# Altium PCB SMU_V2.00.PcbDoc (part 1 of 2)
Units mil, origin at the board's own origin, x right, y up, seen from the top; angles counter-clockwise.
Board outline 8661.42 x 7437.01 mil, 4 copper layers (Component Side, Ground Plane, Power Plane, Solder Side), stack 33.234 mil thick; 223 components, 143 nets, 756 pads, 732 vias.
Unrouted connection lines stored in the file: 6.
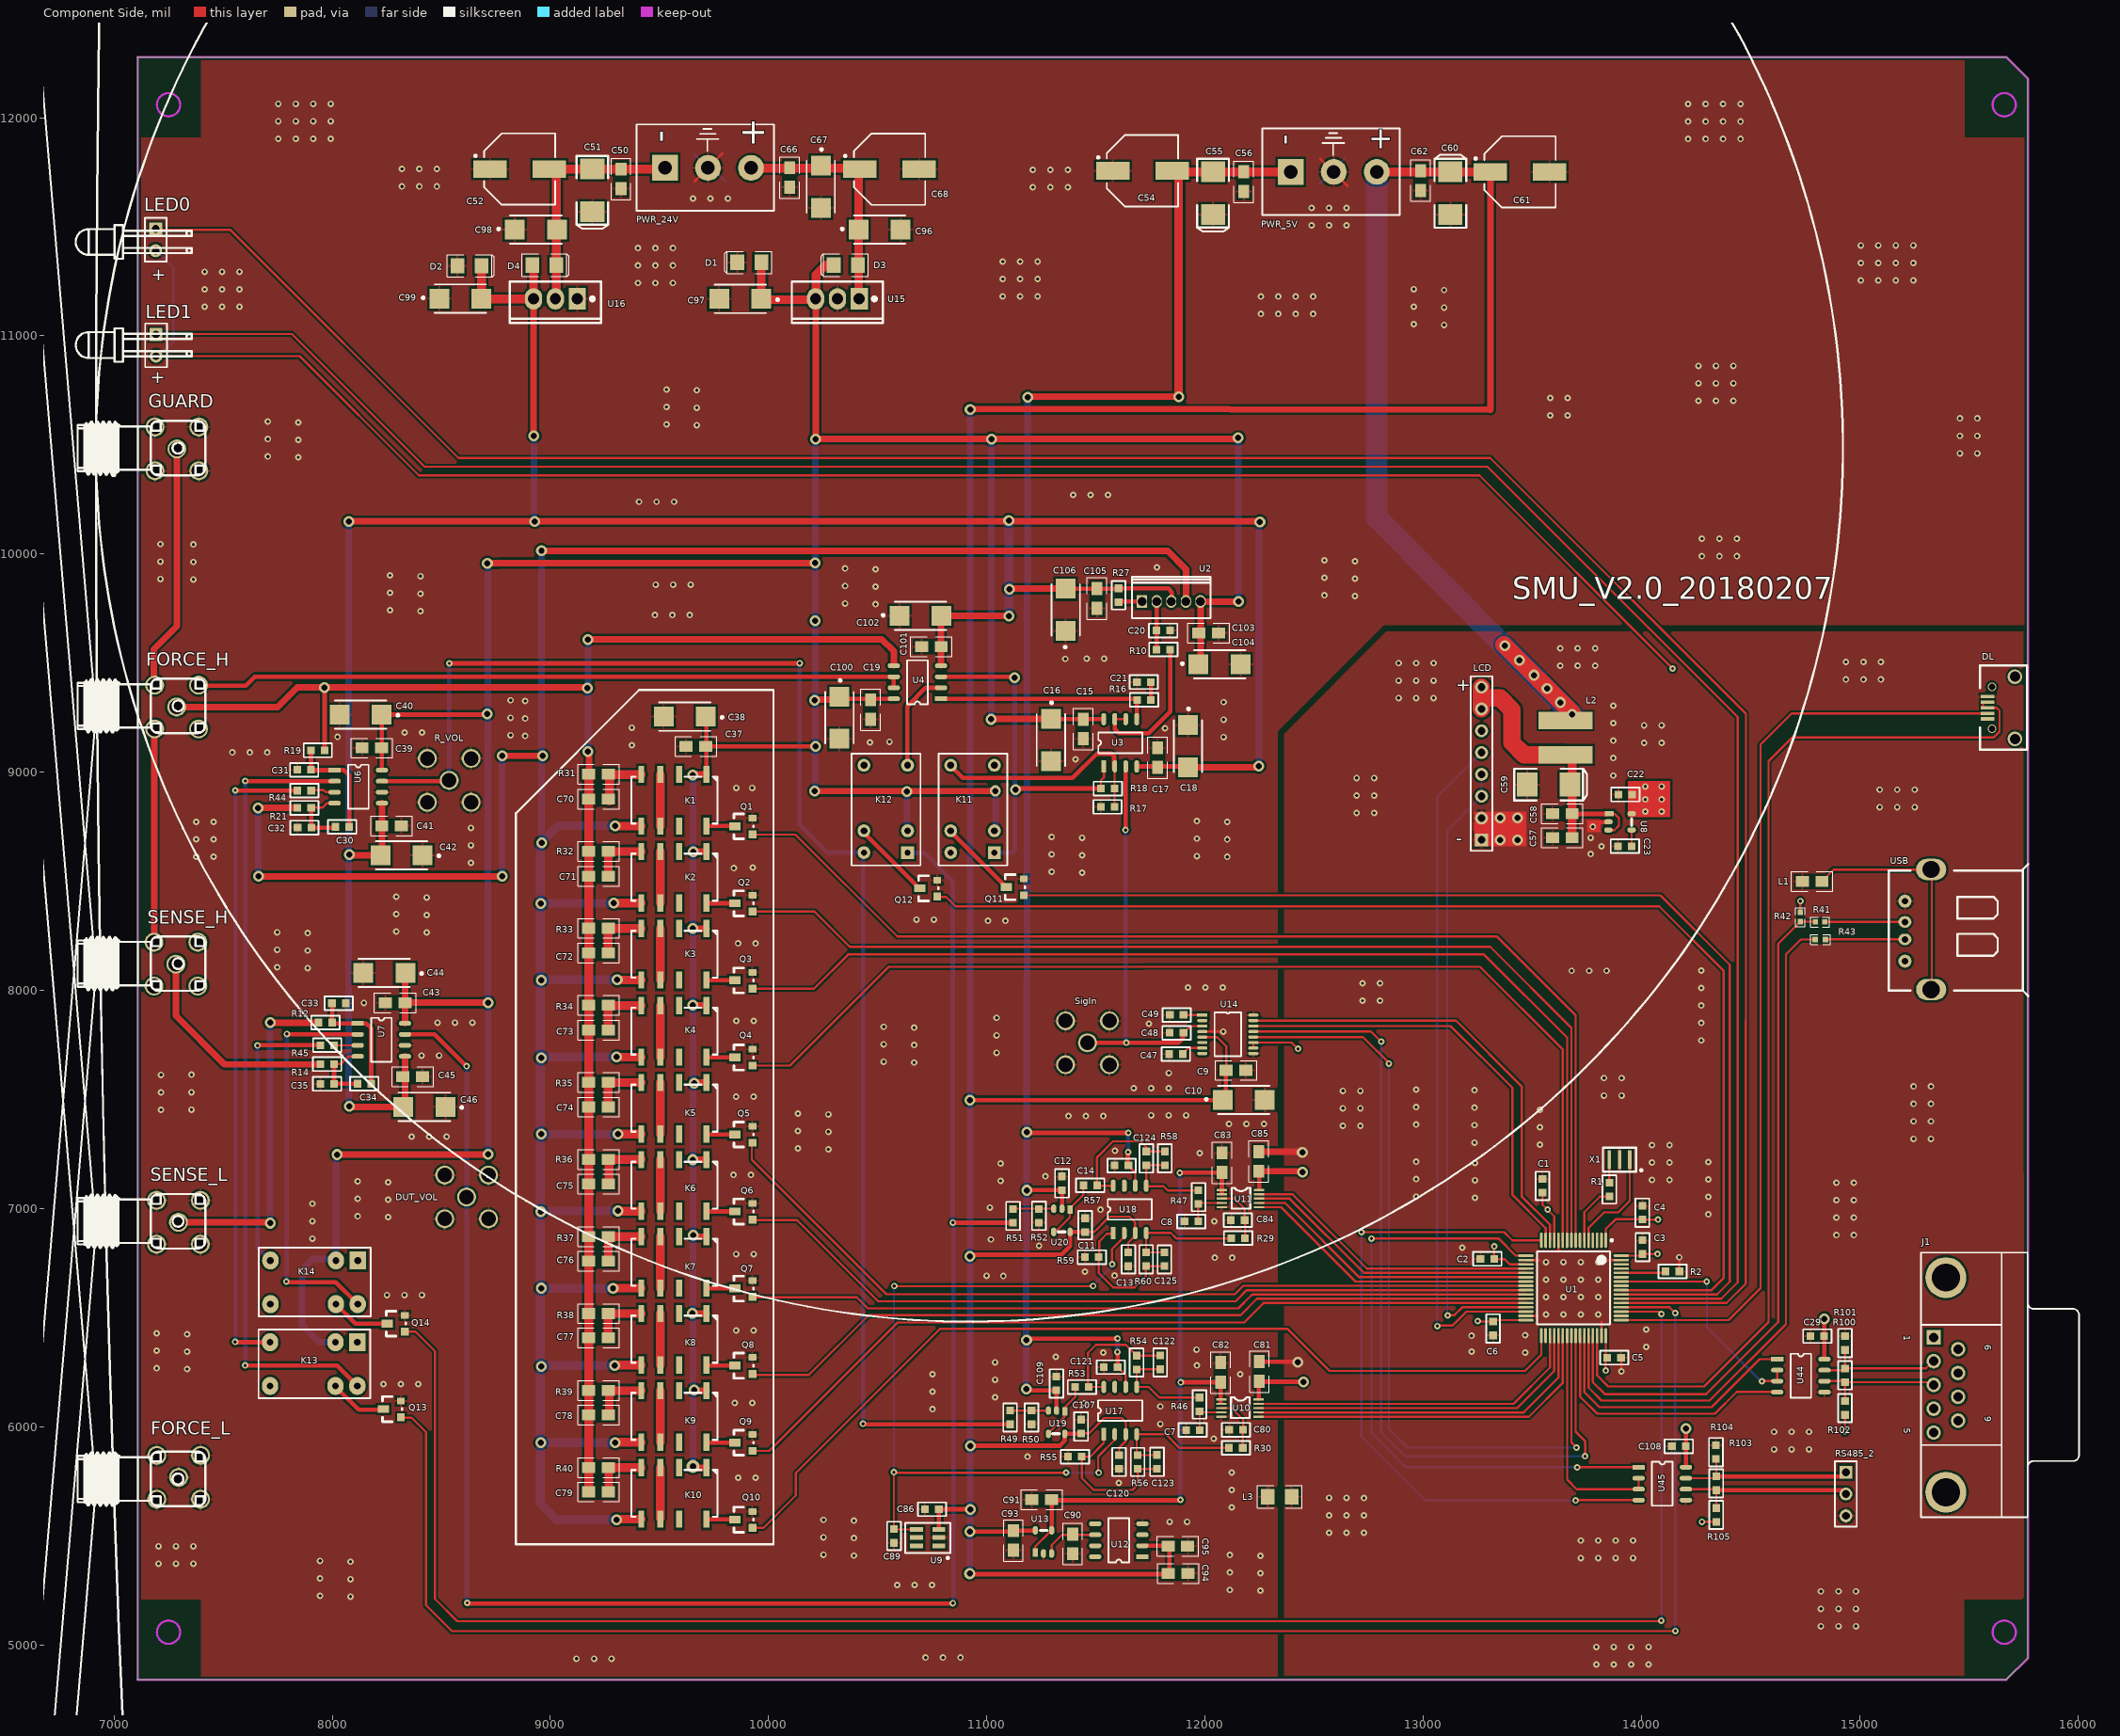
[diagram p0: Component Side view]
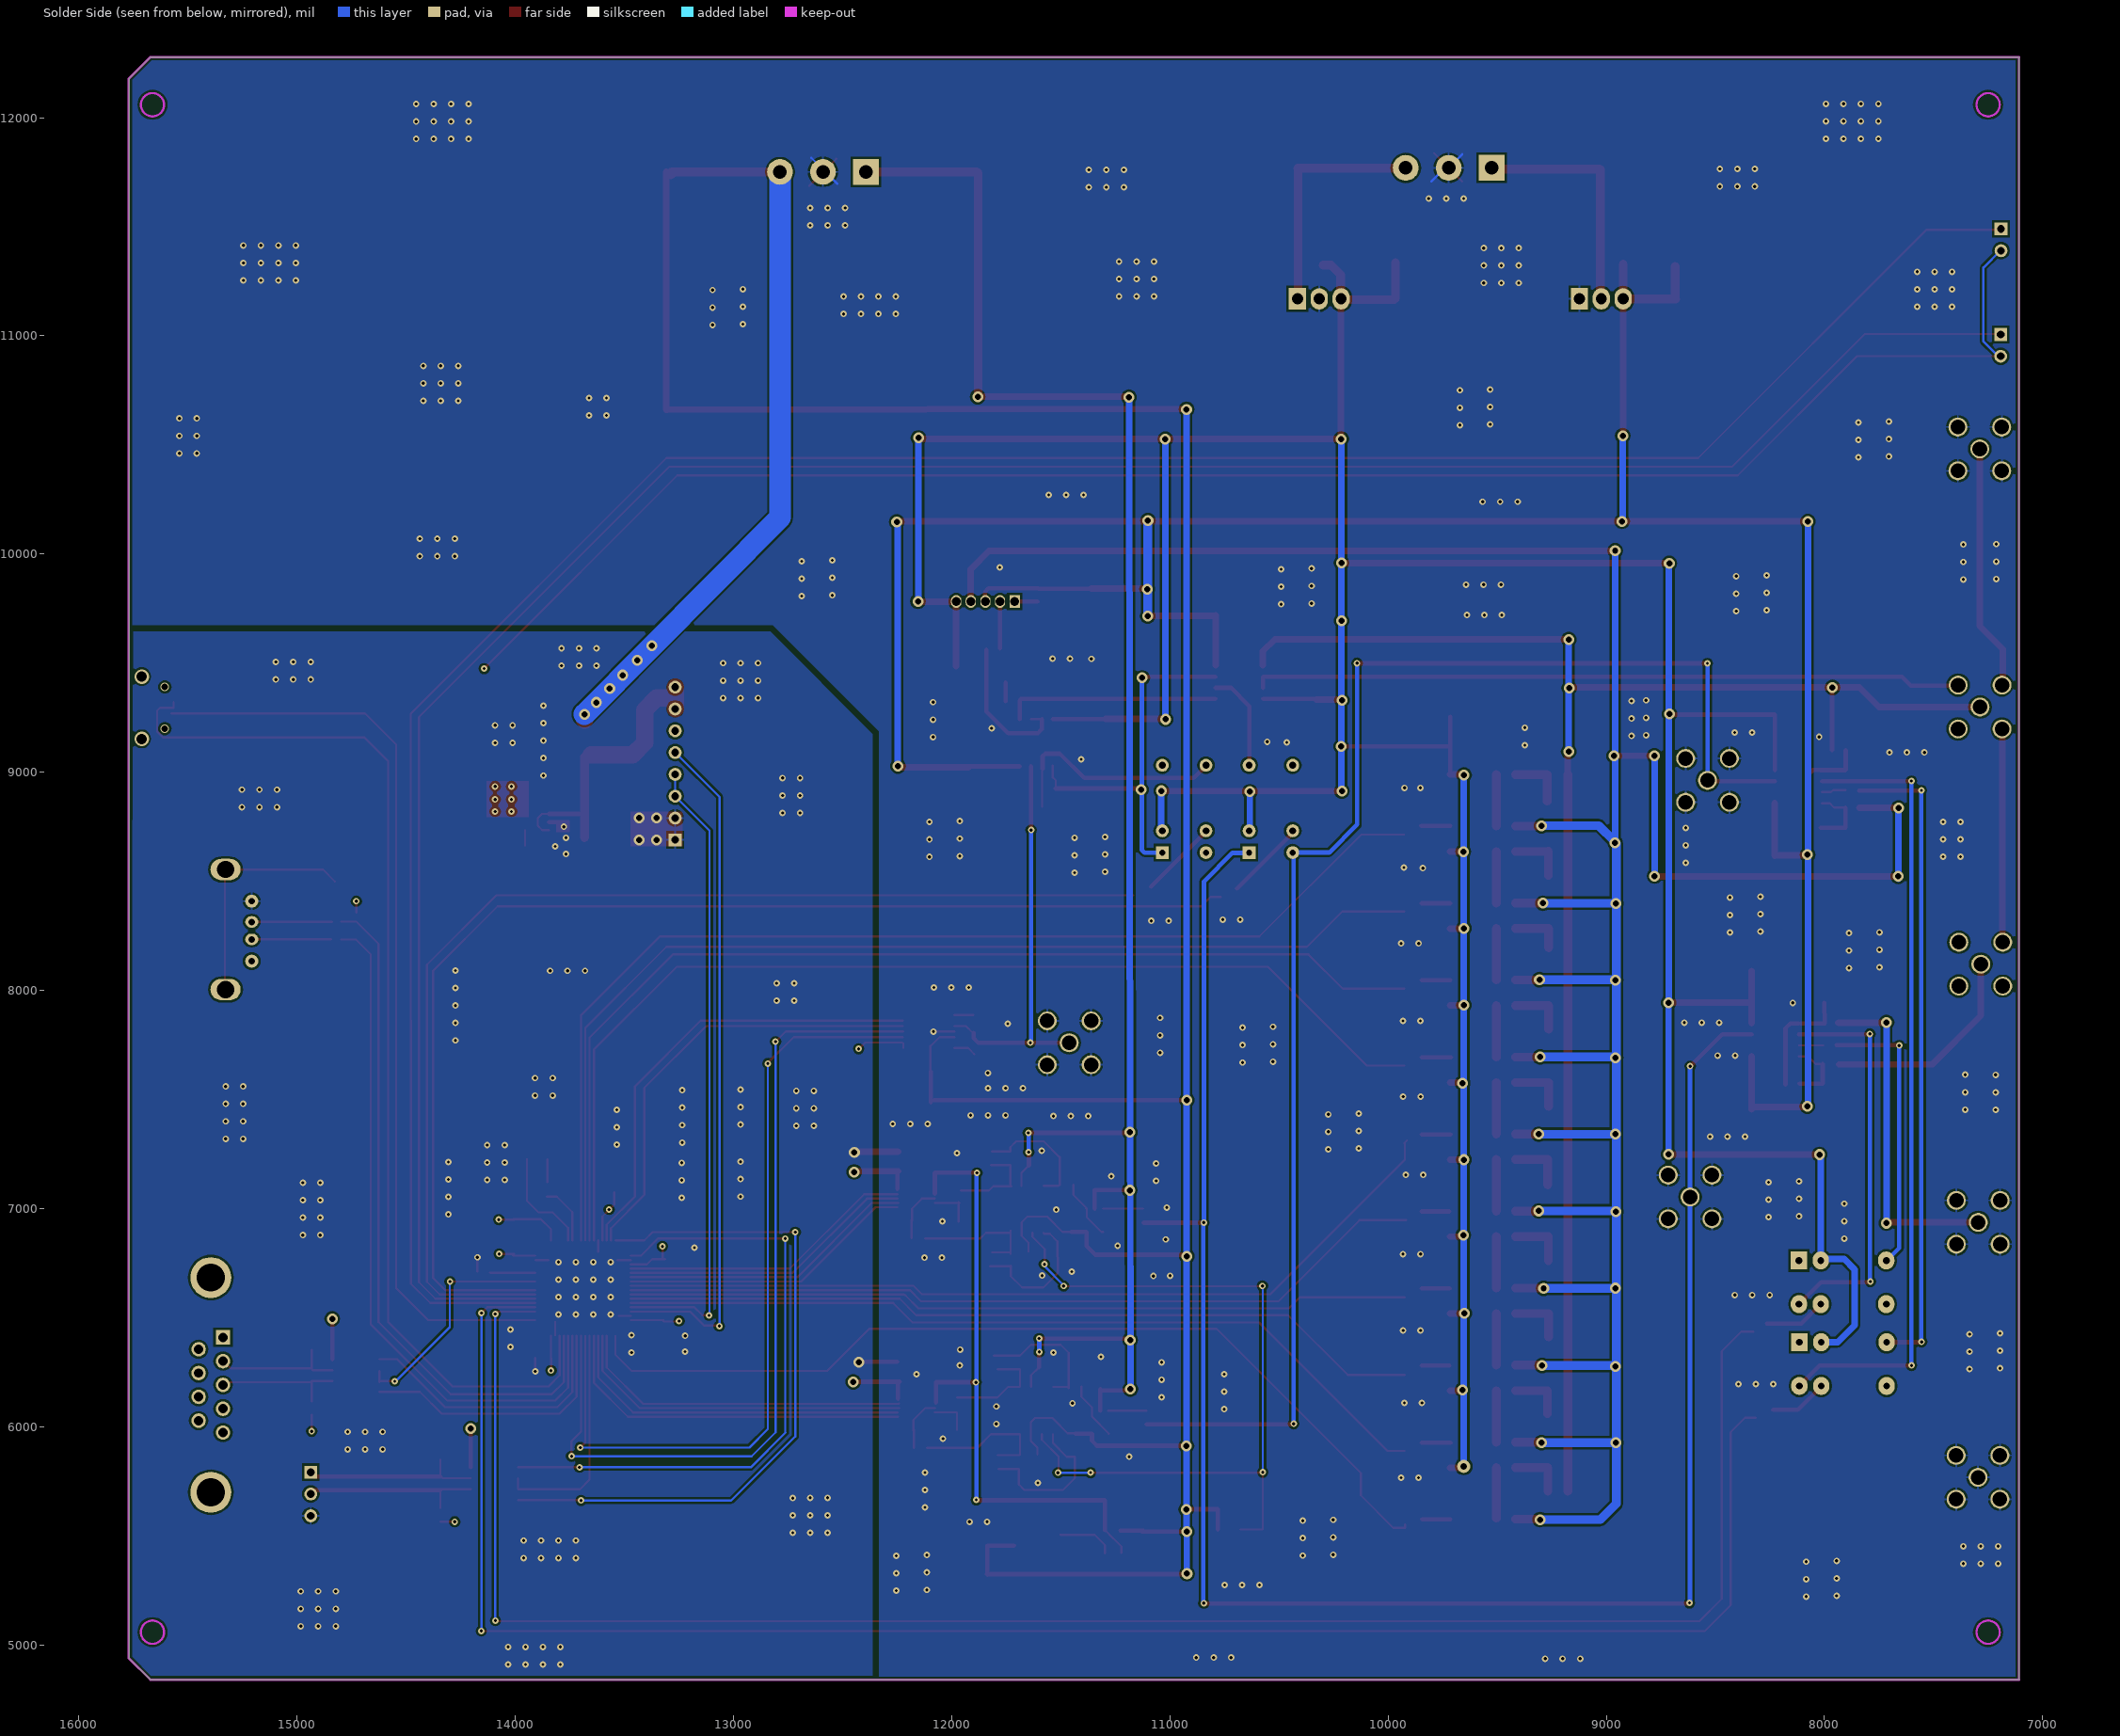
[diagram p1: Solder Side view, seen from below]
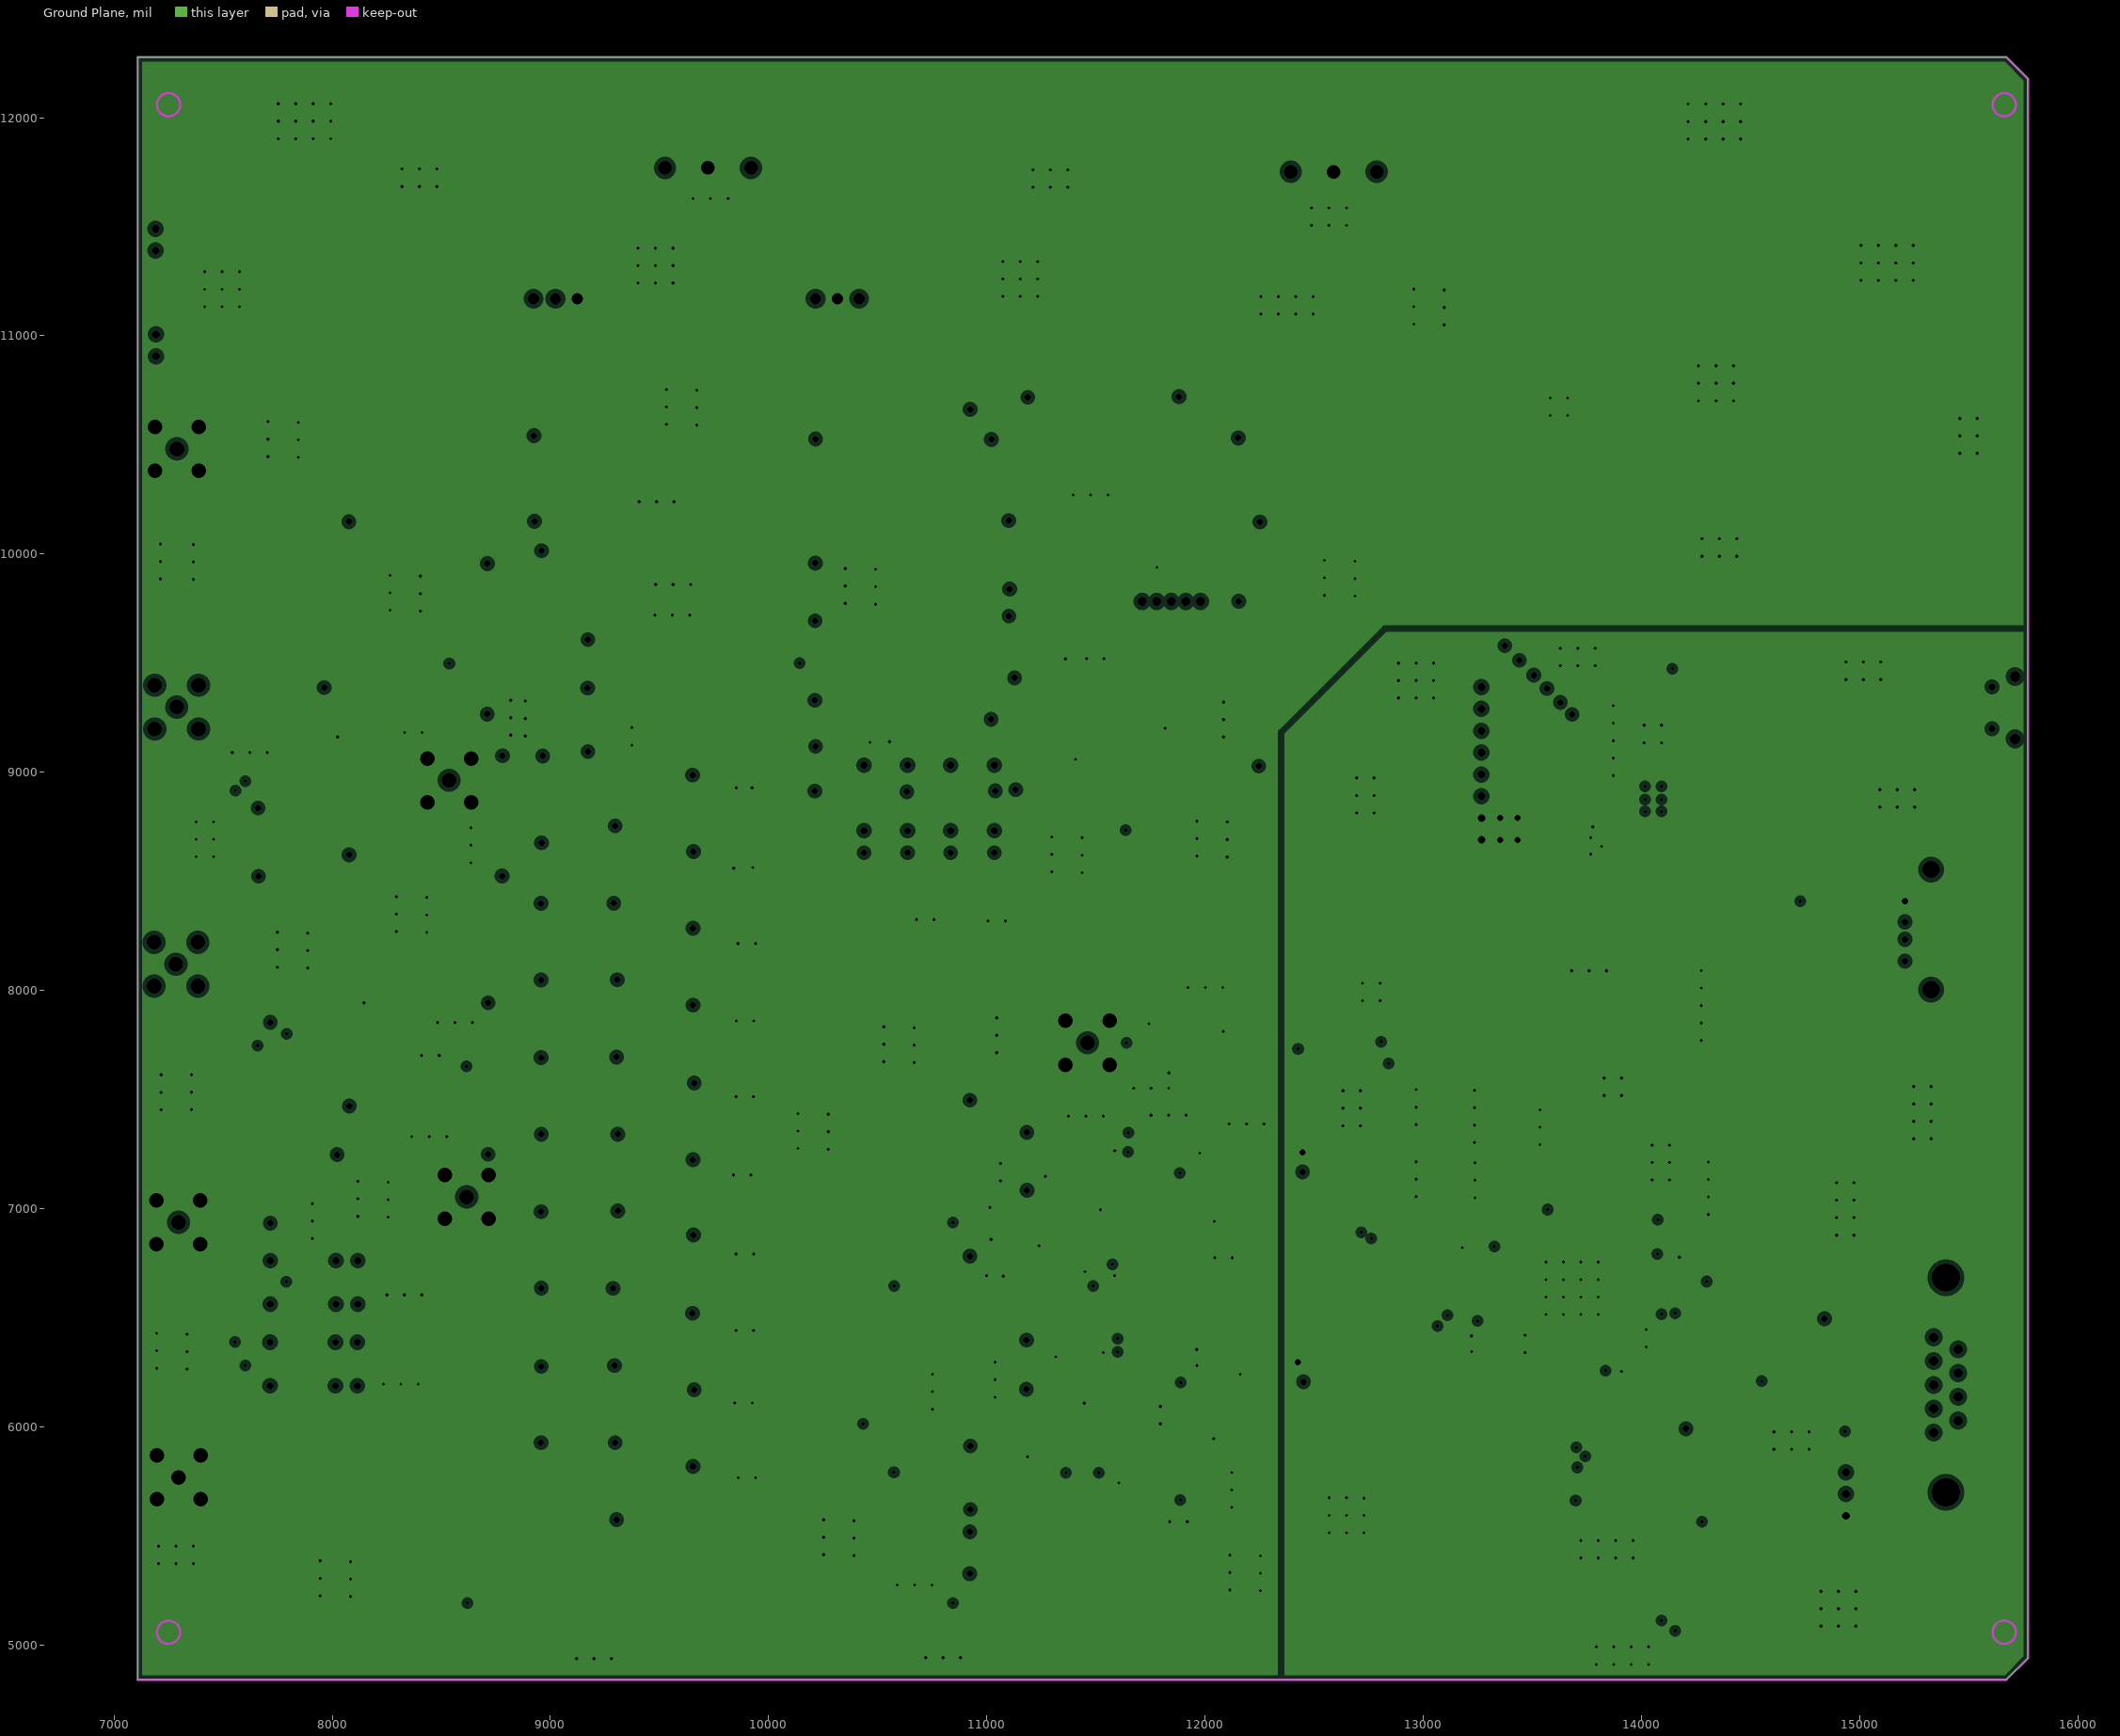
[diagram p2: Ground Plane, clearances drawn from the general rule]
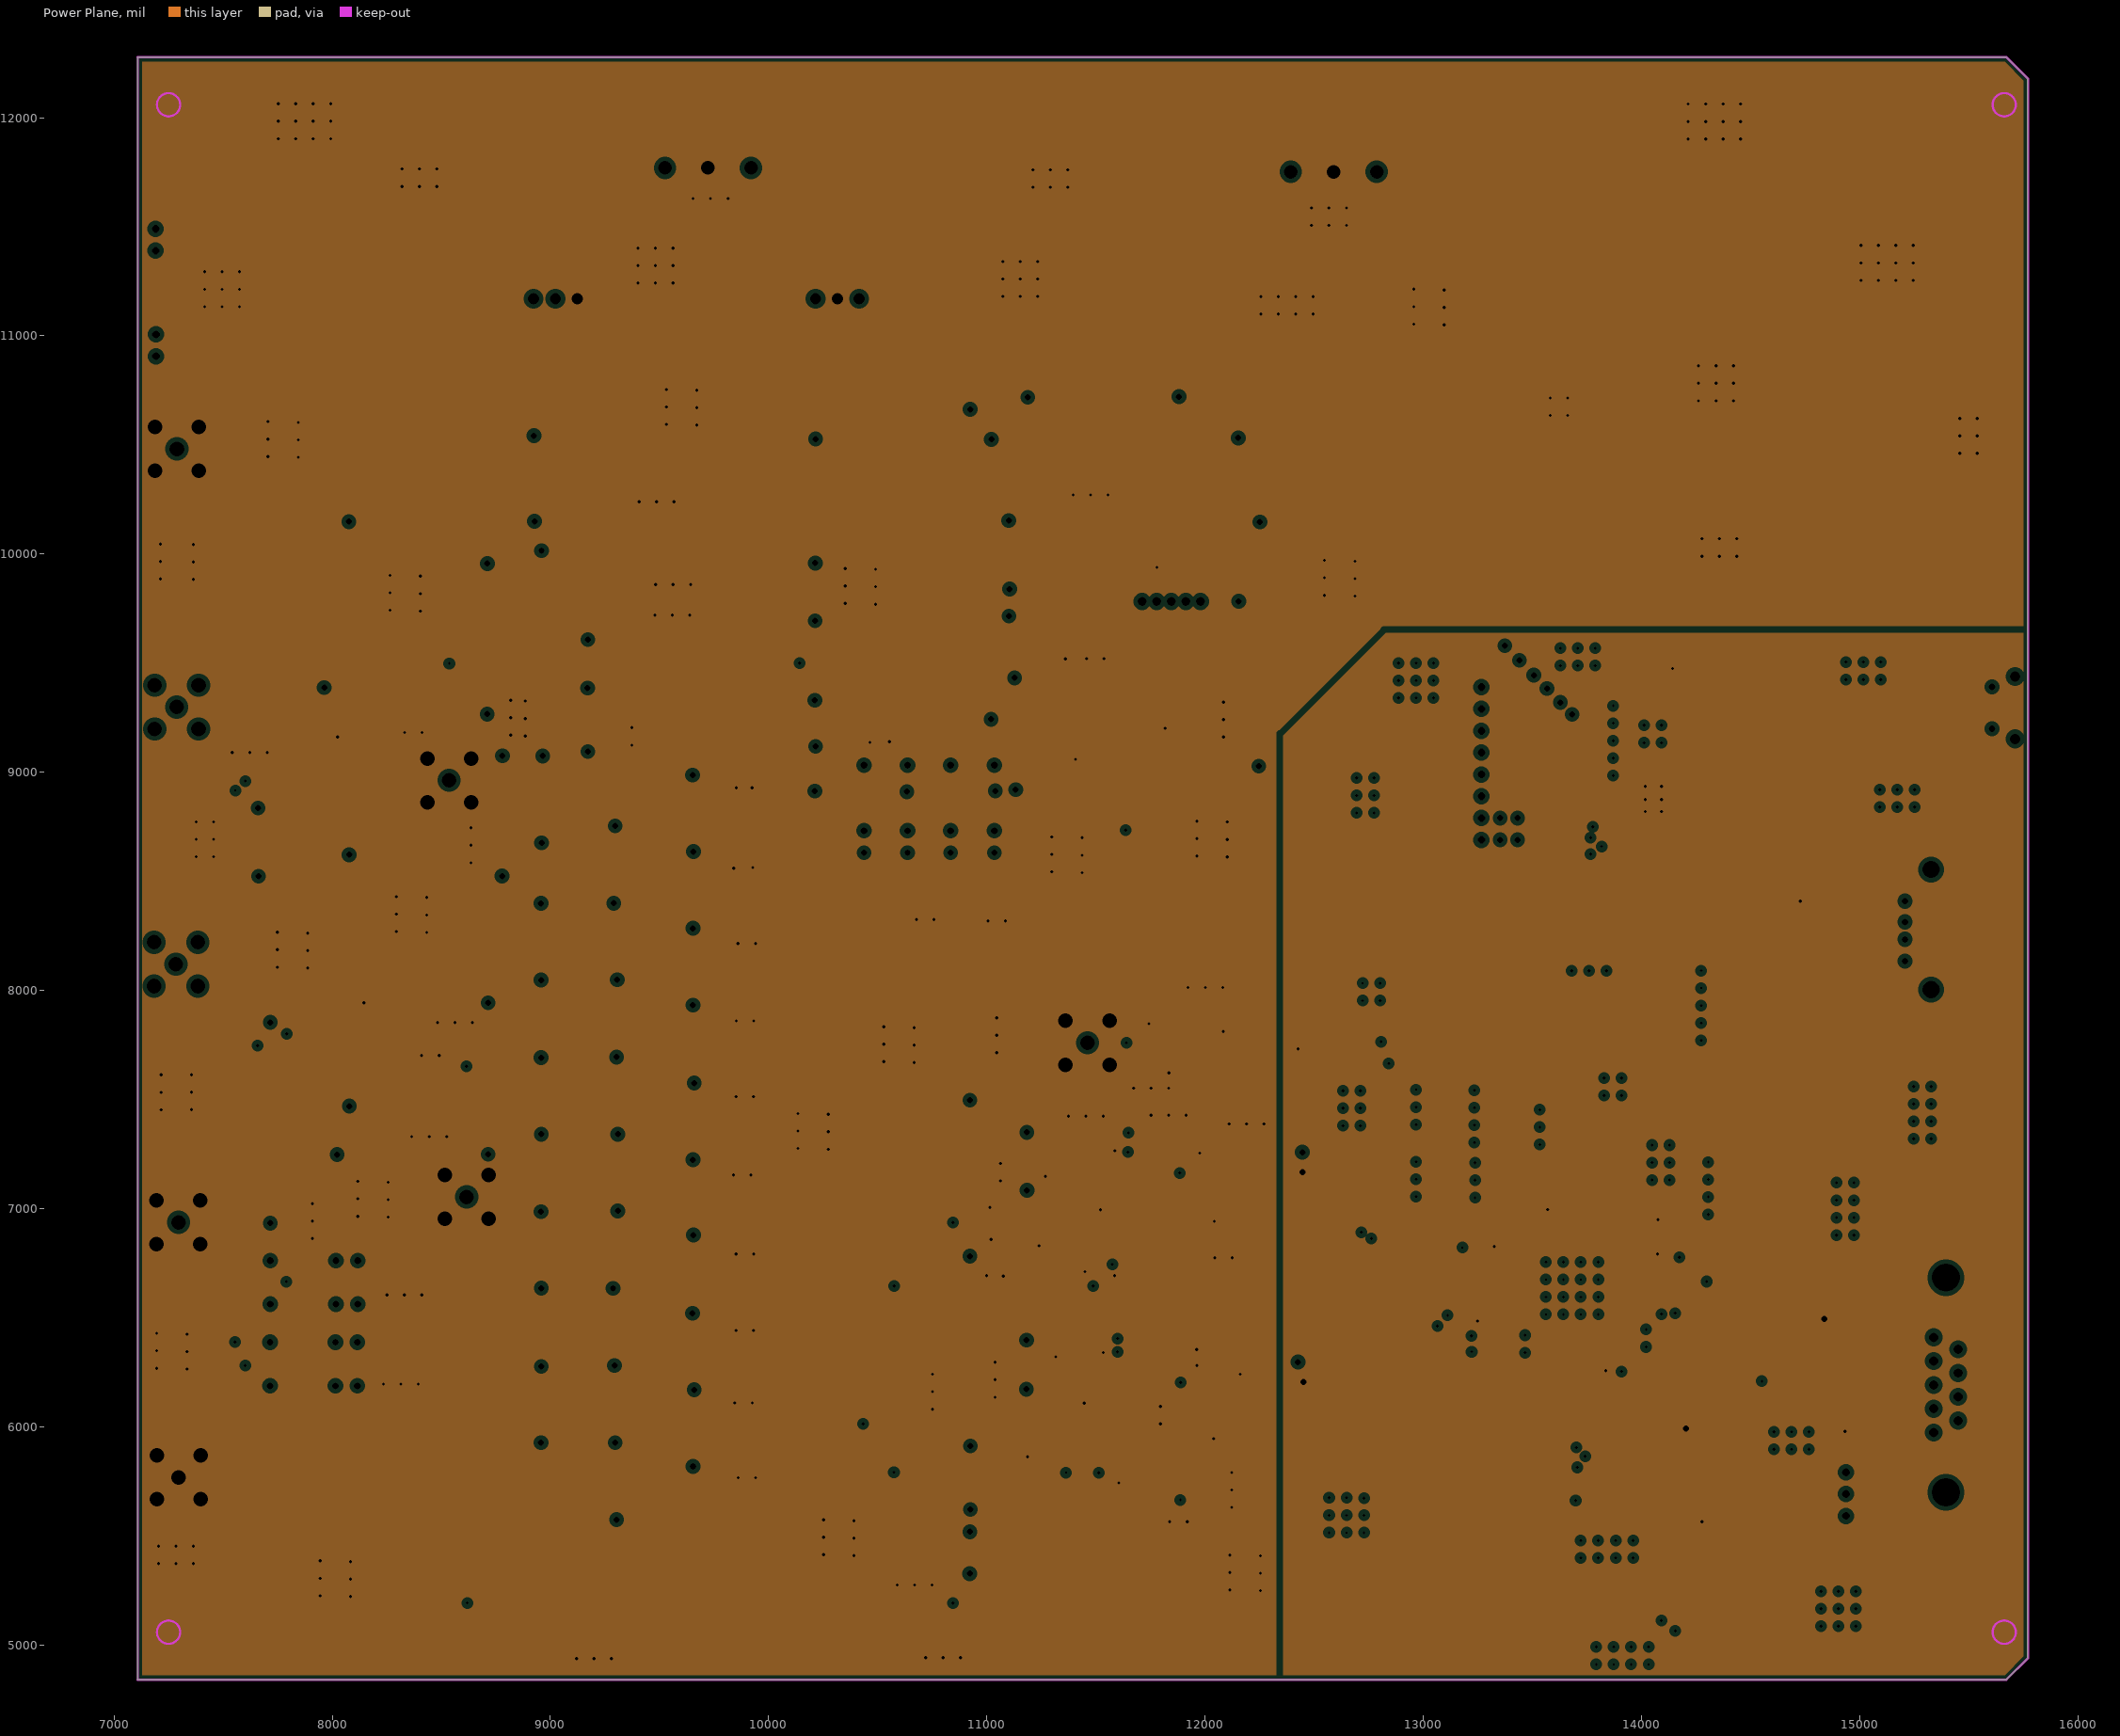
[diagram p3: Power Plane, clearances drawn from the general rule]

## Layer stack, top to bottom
Top Solder: solder mask 0.4, Solder Resist, Dk 3.5
Component Side: signal copper 1.4
Dielectric 1: core 12.6, FR-4, Dk 4.8
Ground Plane: plane copper 1.417, net (Multiple Nets)
Dielectric 3: prepreg 5, Dk 4.2
Power Plane: plane copper 1.417, net (Multiple Nets)
Dielectric 4: core 10, Dk 4.2
Solder Side: signal copper 1.4
Bottom Solder: solder mask 0.4, Solder Resist, Dk 3.5

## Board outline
7108.64,4840.98 15671.64,4840.98 15770.06,4939.41 15770.06,12179.56 15671.64,12277.99 7108.64,12277.99

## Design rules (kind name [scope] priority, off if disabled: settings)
Clearance [All] p1: gap=5
ComponentClearance [All] p1: gap=0 collisioncheckmode=3 verticalgap=0 showdistances=FALSE
PlaneClearance [All] p1: clearance=20
PlaneConnect PlaneConnect_GROUND [All] p1: planeconnectstyle=Relief reliefexpansion=20 reliefentries=4 reliefconductorwidth=10 reliefairgap=10
PlaneConnect "PlaneConnect _POWER" [All] p2: planeconnectstyle=Relief reliefexpansion=20 reliefentries=4 reliefconductorwidth=10 reliefairgap=10
PolygonConnect [IsVia] p1: connectstyle=Direct reliefconductorwidth=10 reliefentries=4 polygonreliefangle="90 Angle" airgapwidth=10
PolygonConnect PolygonConnect_1 [InNet('DGND')] p2: connectstyle=Relief reliefconductorwidth=10 reliefentries=4 polygonreliefangle="90 Angle" airgapwidth=10
PolygonConnect PolygonConnect_2 [InNet('AGND')] p3: connectstyle=Relief reliefconductorwidth=10 reliefentries=4 polygonreliefangle="90 Angle" airgapwidth=10
RoutingVias [All] p1: holewidth=28 width=50 viastyle="Through Hole" minholewidth=28 minwidth=50 maxholewidth=28 maxwidth=50
SolderMaskExpansion [All] p1: expansion=4
UnpouredPolygon UnpouredPolygon_1 [All] p1:
Width [All] p1: maxlimit=100 minlimit=10 preferedwidth=10
26 further rules are at their usual default settings.

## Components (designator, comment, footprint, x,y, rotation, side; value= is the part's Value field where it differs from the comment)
C1 "100nF" 0603 13550.48,7043.53 r180 top
C2 "100nF" 0603 13354.54,6774.4 r270 top
C3 "100nF" 0603 14009.16,6762.3 r180 top
C4 "100nF" 0603 14008.06,6920.52 r180 top
C5 "100nF" 0603 13813.66,6312.96 r90 top
C6 "1uF" 0603 13315.34,6512.26 r0 top
C7 "22nF" 0603 11882.4,5981.19 r90 top
C8 "22nF" 0603 11875.54,6937.09 r90 top
C9 "100nF" 0805#1 12184.03,7609.44 r0 top
C10 "10uF" 6032_pol 12292.92,7453.09 r0 top
C11 "100nF" 0603 11454.89,6863.23 r180 top
C12 "100nF" 0603 11348.18,7055.05 r180 top
C13 "100nF" 0603 11644.29,6829.03 r0 top
C14 "100nF" 0603 11678.49,7202.22 r270 top
C15 "100nF" 0805#1 11416.13,9156.56 r270 top
C16 "10uF" 6032_pol 11248.58,9031.66 r270 top
C17 "100nF" 0805#1 11807.86,9109.09 r90 top
C18 "10uF" 6032_pol 11876.45,9003.67 r270 top
C19 "100nF" 0805#1 10441.9,9245.11 r270 top
C20 "8pF" 0603 11746.73,9645.55 r90 top
C21 "3.3nF" 0603 11657.78,9409.23 r90 top
C22 "1uF" 0603 13987.23,8902.48 r270 top
C23 "22nF" 0603 13985.05,8665.49 r270 top
C29 "100nF" 0603 14866.88,6420.31 r270 top
C30 "10nF" 0603 7984.3,8745.72 r90 top
C31 "1nF" 0603 7932.26,9015.45 r270 top
C32 "1nF" 0603 7811.49,8742.25 r90 top
C33 "1nF" 0603 7968.67,7937.21 r90 top
C34 "10nF" 0603 8085.84,7568.45 r90 top
C35 "1nF" 0603 7915.59,7567.97 r90 top
C37 "100nF" 0805#1 9624.82,9143.09 r180 top
C38 "10uF" 6032_pol 9499.21,9300.12 r180 top
C39 "100nF" 0805#2 8226.39,9111.4 r180 top
C40 "10uF" 6032_pol 8013.68,9309.33 r180 top
C41 "100nF" 0805#2 8227.07,8754.91 r0 top
C42 "10uF" 6032_pol 8201.7,8664.82 r180 top
C43 "100nF" 0805#1 8246.53,7968.98 r180 top
C44 "10uF" 6032_pol 8122.63,8125.71 r180 top
C45 "100nF" 0805#1 8410.81,7580.34 r0 top
C46 "10uF" 6032_pol 8306.13,7511.95 r180 top
C47 "100nF" 0603 11804.95,7704.61 r90 top
C48 "100nF" 0603 11808.14,7801.76 r90 top
C49 "100nF" 0603 11808.57,7883.63 r90 top
C50 "100nF" 0805#2 9323.53,11674.48 r90 top
C51 "10uF" 6032_POL 9193.53,11669.48 r270 top
C52 "47uF" cap_pol_8*10.2#1 8858.53,11764.48 r0 top
C54 "47uF,50V" cap_pol_8*10.2#1 11712.82,11756.73 r0 top
C55 "10uF" 6032_POL 12037.82,11656.73 r270 top
C56 "1uF" 0805#2 12177.82,11751.73 r270 top
C57 "100nF" 0805#2 13681.88,8700.31 r180 top
C58 "1uF" 0805#2 13681.88,8810.31 r180 top
C59 "10uF" 6032_POL 13571.88,8945.31 r0 top
C60 "10uF" 6032_POL 13122.82,11651.73 r90 top
C61 "47uF,50V" cap_pol_8*10.2#1 13442.82,11751.73 r0 top
C62 "1uF" 0805#2 12987.82,11756.73 r270 top
C66 "100nF" 0805#2 10096.06,11680.72 r90 top
C67 "10uF" 6032_pol 10193.75,11567.54 r270 top
C68 "47uF" cap_pol_8*10.2#2 10553.42,11764.23 r90 top
C70 "10uF" 0805#1 9178.42,8902.04 r180 top
C71 "1uF" 0805#1 9178.42,8549.31 r180 top
C72 "100nF" 0805#1 9178.42,8196.58 r180 top
C73 "10nF" 0805#1 9178.42,7843.86 r180 top
C74 "1nF" 0805#1 9178.42,7491.13 r180 top
C75 "100pF" 0805#1 9178.42,7138.4 r180 top
C76 "10pF" 0805#1 9178.42,6785.67 r180 top
C77 "1pF" 0805#2 9265.42,6407.94 r180 top
C78 "NULL" 0805#1 9178.42,6080.22 r180 top
C79 "NULL" 0805#1 9178.42,5727.49 r180 top
C80 "22nF" 0603 12080.3,5982.16 r90 top
C81 "100nF" 0805#1 12274.04,6296.06 r90 top
C82 "10uF" 0805#1 12045.94,6207.55 r270 top
C83 "10uF" 0805#2 12077.33,7255.92 r270 top
C84 "22nF" 0603 12088.73,6943.37 r90 top
C85 "100nF" 0805#2 12245.91,7171.67 r90 top
C86 "100nF" 0603 10809.48,5626.86 r270 top
C89 "100nF" 0603 10570.26,5561.34 r0 top
C90 "100nF" 0805#2 11393.28,5508.88 r270 top
C91 "100nF" 0805#2 11296.36,5666.09 r180 top
C93 "100nF" 0805#1 11146.77,5521.52 r90 top
C94 "100nF" 0805#1 11918.59,5303.91 r0 top
C95 "100nF" 0805#1 11917.27,5428.74 r0 top
C96 "4.7uF" 6032_pol 10624.6,11441.96 r0 top
C97 "4.7uF" 6032_pol 9753.6,11214.42 r180 top
C98 "4.7uF" 6032_pol 9048.98,11441.96 r0 top
C99 "4.7uF" 6032_pol 8703.55,11126.27 r0 top
C100 "10uF" 6032_pol 10279.34,9133.91 r270 top
C101 "100nF" 0805#1 10703.53,9600.98 r180 top
C102 "10uF" 6032_pol 10811.76,9671.85 r0 top
C103 "100nF" 0805#1 12058.52,9613.88 r0 top
C104 "10uF" 6032_pol 12182.34,9449.82 r0 top
C105 "100nF" 0805#1 11480.12,9754.83 r270 top
C106 "10uF" 6032_pol 11406.43,9860.79 r90 top
C107 "100nF" 0603 11436.13,5940.36 r180 top
C108 "100nF" 0603 14231.88,5915.31 r270 top
C109 "100nF" 0603 11322.89,6137.89 r180 top
C120 "100nF" 0603 11601.62,5900.24 r0 top
C121 "100nF" 0603 11628.84,6277.88 r270 top
C122 "1pF" 0603 11798.58,6234.05 r180 top
C123 "1pF" 0603 11783.84,5778.76 r180 top
C124 "1pF" 0603 11735.02,7169.53 r180 top
C125 "1pF" 0603 11817.88,6706.77 r180 top
D1 "Diode 1N4007" 1206_LED 9858.18,11336.6 r0 top
D2 "Diode 1N4007" 1206_LED 8682.03,11321.26 r180 top
D3 "Diode 1N4007" 1206_LED 10300.04,11324.4 r0 top
D4 "Diode 1N4007" 1206_LED 9025.66,11324.4 r180 top
DL "USB_5pin" USBmicro_B 15691,9305.31 r270 top
DUT_VOL "SMB" SMA 8515.34,7154.03 r0 top
FORCE_H "SMB" SMA 7186.47,9399.39 r0 top
FORCE_L "SMB" SMA 7195.73,5869.31 r0 top
GUARD "SMB" SMA 7187.68,10582.57 r0 top
J1 "USART" DSUB1.385-2H9 15768.88,6192.26 r270 top
K1 "AXICOM IM" AXICOM_IM06 9590.6,8865 r180 top
K2 "AXICOM IM" AXICOM_IM06 9590.6,8512.03 r180 top
K3 "AXICOM IM" AXICOM_IM06 9590.6,8159.06 r180 top
K4 "AXICOM IM" AXICOM_IM06 9590.6,7806.09 r180 top
K5 "AXICOM IM" AXICOM_IM06 9590.6,7453.12 r180 top
K6 "AXICOM IM" AXICOM_IM06 9590.6,7100.15 r180 top
K7 "AXICOM IM" AXICOM_IM06 9590.6,6747.18 r180 top
K8 "AXICOM IM" AXICOM_IM06 9590.6,6394.2 r180 top
K9 "AXICOM IM" AXICOM_IM06 9590.6,6041.23 r180 top
K10 "AXICOM IM" AXICOM_IM06 9590.6,5688.26 r180 top
K11 "Relay" Relay_OMRON5V#1 11034.46,8632.05 r180 top
K12 "Relay" Relay_OMRON5V#1 10636.55,8632.05 r180 top
K13 "Relay" Relay_OMRON5V#2 8114.82,6387.86 r270 top
K14 "Relay" Relay_OMRON5V#2 8116.68,6762.69 r270 top
L1 "10uH" 0805#2 14736.88,8500.31 r0 top
L2 "10uH" 8040 13651.88,9080.31 r0 top
L3 "10uH" 1206 12286.48,5679.69 r0 top
LCD "Header 8" HDR1X8 13266.88,8690.31 r90 top
LED0 "Header 2" HDR1X2 7190.85,11490.63 r270 top
LED1 "Header 2" HDR1X2 7192.45,11006.75 r270 top
PWR_5V "Header 3" PWR_3T 12392.82,11751.73 r90 top
PWR_24V "Header 3" PWR_3T 9525.2,11770.04 r90 top
Q1 "NUD3112" SOT_23 9925.06,8722.04 r0 top
Q2 "NUD3112" SOT_23 9925.06,8368.95 r0 top
Q3 "NUD3112" SOT_23 9925.06,8015.87 r0 top
Q4 "NUD3112" SOT_23 9925.06,7662.79 r0 top
Q5 "NUD3112" SOT_23 9925.06,7309.7 r0 top
Q6 "NUD3112" SOT_23 9925.06,6956.62 r0 top
Q7 "NUD3112" SOT_23 9925.06,6603.54 r0 top
Q8 "NUD3112" SOT_23 9925.06,6250.45 r0 top
Q9 "NUD3112" SOT_23 9925.06,5897.37 r0 top
Q10 "NUD3112" SOT_23 9925.06,5544.29 r0 top
Q11 "NUD3112" SOT_23 11168.91,8443.48 r0 top
Q12 "NUD3112" SOT_23 10772.28,8437.97 r0 top
Q13 "NUD3112" SOT_23 8314.41,6051.05 r0 top
Q14 "NUD3112" SOT_23 8331.76,6443.14 r0 top
R1 "100R" 0603 13857.39,7026.81 r180 top
R2 "10K" 0603 14203.34,6716.68 r270 top
R10 "1K" 0603 11747.69,9558.22 r90 top
R12 "1K" 0603 8029.68,7857.14 r270 top
R14 "1K" 0603 8037.75,7666.99 r270 top
R16 "100K" 0603 11781.43,9336.14 r270 top
R17 "1K" 0603 11492.11,8837.37 r90 top
R18 "4.99K" 0603 11615.61,8929.81 r270 top
R19 "2.2K" 0603 7994.92,9105.19 r270 top
R21 "2.2K" 0603 7810.96,8832.96 r90 top
R27 "100R" 0603 11607.98,9750.39 r180 top
R29 "1K" 0603 12212.66,6869.49 r270 top
R30 "1K" 0603 12202.41,5908.44 r270 top
R31 "1R" 0805#1 9178.42,9016.57 r180 top
R32 "10R" 0805#1 9178.42,8663.41 r180 top
R33 "100R" 0805#1 9178.42,8310.25 r180 top
R34 "1K" 0805#2 9265.42,7932.09 r180 top
R35 "10K" 0805#2 9265.42,7578.92 r180 top
R36 "100K" 0805#2 9265.42,7225.76 r180 top
R37 "1M" 0805#2 9265.42,6872.6 r180 top
R38 "10M" 0805#1 9178.42,6544.44 r180 top
R39 "100M" 0805#1 9178.42,6191.28 r180 top
R40 "1G" 0805#1 9178.42,5838.12 r180 top
R41 "22R" 0402#1 14711.88,8310.31 r90 top
R42 "1.5K" 0402#1 14731.88,8230.31 r180 top
R43 "22R" 0402#2 14715.42,8230.07 r90 top
R44 "2.2K" 0603 7933.32,8920.41 r270 top
R45 "2.2K" 0603 8038.02,7753.56 r270 top
R46 "1K" 0603 11978.65,6041.75 r180 top
R47 "1K" 0603 11974.02,6992.07 r180 top
R49 "11K" 0603 11110.81,5982.03 r180 top
R50 "1K" 0603 11200.58,6104.36 r0 top
R51 "11K" 0603 11124.07,6905.81 r180 top
R52 "1K" 0603 11234.38,7028.29 r0 top
R53 "1K" 0603 11374.51,6178.56 r90 top
R54 "1K" 0603 11682.12,6356.1 r0 top
R55 "1K" 0603 11342.32,5859.03 r90 top
R56 "1K" 0603 11686.49,5900.24 r0 top
R57 "1K" 0603 11412.7,7102.71 r90 top
R58 "1K" 0603 11811.39,7292.08 r0 top
R59 "1K" 0603 11419.96,6773.75 r90 top
R60 "1K" 0603 11725.51,6829.24 r0 top
R100 "120" 0603 14936.88,6175.31 r180 top
R101 "NULL" 0603 14928.38,6445.31 r0 top
R102 "NULL" 0603 14936.88,6025.31 r180 top
R103 "120" 0603 14346.88,5680.31 r180 top
R104 "NULL" 0603 14336.88,5945.31 r0 top
R105 "NULL" 0603 14346.88,5535.31 r180 top
R_VOL "SMB" SMA 8435.42,9063.66 r0 top
RS485_2 "Header 3" HDR1X3 14936.81,5792.26 r270 top
SENSE_H "SMB" SMA 7183.17,8220.98 r0 top
SENSE_L "SMB" SMA 7194.97,7038 r0 top
SigIn "SMB" SMA 11360.79,7860.75 r0 top
U1 "STM32F103RET6" LQFP64_N 13681.88,6635.31 r90 top
U2 "BUF634" PSFM-T5 11711.2,9782.7 r90 top
U3 "AD4522-2" SO-8N#1 11665.73,9184.94 r90 top
U4 "AD4522-2" SO-8N#1 10631.97,9466.99 r180 top
U6 "AD8422ARZ" SO-8N#1 8169,8879.71 r0 top
U7 "AD8422ARZ" SO-8N#1 8274.7,7719.28 r0 top
U8 "RT9193" SOT-23-5 13895.71,8771.26 r270 top
U9 "ADR127-1.25" SOT_UJ6 10730.26,5486.34 r90 top
U10 "AD7988-1" MSOP10 12169.37,6053.59 r0 top
U11 "AD7988-1" MSOP10 12171.78,7013.54 r0 top
U12 "ADR441" SO-8N#1 11554.87,5534.77 r180 top
U13 "AD8601" SOT-23-5 11261.12,5467.06 r0 top
U14 "AD5689R" TSSOP16 11988.04,7888.42 r0 top
U15 "7815" TO-220 10314.11,11169.72 r180 top
U16 "7915" TO-220 9021.53,11169.72 r180 top
U17 "AD8137" SO-8N#1 11665.61,6124.4 r90 top
U18 "AD8137" SO-8N#1 11709.13,7046.8 r90 top
U19 "ADA4000-1" SOT-23-5 11317.61,6027.37 r180 top
U20 "ADA4000-1" SOT-23-5 11342.29,6952.45 r180 top
U44 "SP3485" SO-8N#2 14621.88,6310.31 r0 top
U45 "SP3485" SO-8N#2 13986.88,5815.31 r0 top
USB "USB" USB_A 15415.03,8315.31 r0 top
X1 "8M smd" 8Mhz_XTAL 13946.36,7225.16 r180 top

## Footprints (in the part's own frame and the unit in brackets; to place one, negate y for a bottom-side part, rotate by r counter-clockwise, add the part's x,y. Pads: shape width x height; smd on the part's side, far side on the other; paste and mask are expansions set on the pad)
8Mhz_XTAL [mm]
  rect 0.4x2.2 smd: 1(0,0) 2(1.2,0) 3(2.4,0)
  silkscreen extent -1.45,-1.39 3.13,1.4
0402#1 [mil]
  rect 25x25 smd: 1(3.98,-127.99) 2(3.98,-84.98)
  silkscreen extent -19,-150 26,-63
0402#2 [mil]
  rect 25x25 smd: 1(4.06,-127.99) 2(4.06,-80.75)
  silkscreen extent -19,-150 26,-59
0603 [mil]
  rect 35x35 smd: 1(4.25,-92.76) 2(4.25,-29.76)
  silkscreen extent -27,-126 36,4
0805#1 [mil]
  rect 60x50 smd: 1(3,25) 2(-87,25)
  silkscreen extent -137,-20 53,70
0805#2 [mil]
  rect 60x50 smd: 1(90,0) 2(0,0)
  silkscreen extent -50,-45 140,45
1206 [mm]
  rect 1.6x1.8 smd: 1(0,0) 2(2.8,0)
  silkscreen extent -1.2,-1.3 4,1.3
1206_LED [mm]
  rect 1.6x1.8 smd: 1(-0.051,0) 2(2.749,0)
  silkscreen extent -1.52,-1.3 3.95,1.3
6032_pol [mm]
  rect 2.3x2.3 smd: 1(-5.396,1.143) 2(-0.496,1.143)
  silkscreen extent -7.43,-0.51 0.05,2.79
6032_POL [mm]
  rect 2.4x2.8 smd: 1(2.538,-0.041) 2(-2.422,-0.041)
  silkscreen extent -3.95,-1.89 4.53,1.81
8040 [mm]
  rect 6.3x2 smd: 1(0,4) 2(0,0)
AXICOM_IM06 [mm]
  rect 0.7x2 smd: 1(-3.174,-3.174) 2(0.026,-3.174) 3(2.226,-3.174) 4(4.426,-3.174) 5(4.426,2.826) 6(2.226,2.826) 7(0.026,2.826) 8(-3.174,2.826)
  silkscreen extent -4.44,-2.92 5.59,2.54
cap_pol_8*10.2#1 [mm]
  rect 3.9x2.05 smd: 1(-3.443,-0.001) 2(3.457,-0.001)
  silkscreen extent -5.27,-4.15 4.16,4.15
cap_pol_8*10.2#2 [mm]
  rect 2.05x3.9 smd: 1(-0.001,3.443) 1(-0.001,3.443) 2(-0.001,-3.457) 2(-0.001,-3.457)
  silkscreen extent -4.15,-4.16 4.15,5.27
DSUB1.385-2H9 [mm] "Connector; D Subminiature; 9 Position; Right Angle; Pitch 1.385 mm"
  rect 1.69x1.69 hole 1.09: 1(-5.54,-10.92)
  round 1.69 hole 1.09: 2(-2.77,-10.92) 3(0,-10.92) 4(2.77,-10.92) 5(5.54,-10.92) 6(-4.155,-8.08) 7(-1.385,-8.08) 8(1.385,-8.08) 9(4.155,-8.08)
  round 4.76 hole 3.26: 10(-12.495,-9.5) 11(12.495,-9.5)
  silkscreen extent -15.4,-12.4 15.4,6
HDR1X2 [mm] "Connector; Header; 2 Position"
  rect 1.5x1.5 hole 0.9: 1(0,0)
  round 1.5 hole 0.9: 2(2.54,0)
  silkscreen extent -1.27,-1.27 3.81,1.27
HDR1X3 [mm] "Connector; Header; 3 Position"
  rect 1.5x1.5 hole 0.9: 1(0,0)
  round 1.5 hole 0.9: 2(2.54,0) 3(5.08,0)
  silkscreen extent -1.27,-1.27 6.35,1.27
HDR1X8 [mm] "Connector; Header; 8 Position"
  rect 1.5x1.5 hole 0.9: 1(0,0)
  round 1.5 hole 0.9: 2(2.54,0) 3(5.08,0) 4(7.62,0) 5(10.16,0) 6(12.7,0) 7(15.24,0) 8(17.78,0)
  silkscreen extent -1.27,-1.27 19.05,1.27
LQFP64_N [mm]
  oval 1.8x0.3 smd: 1(5.586,-3.921) 2(5.586,-3.421) 3(5.586,-2.921) 4(5.586,-2.421) 5(5.586,-1.921) 6(5.586,-1.421) 7(5.586,-0.921) 8(5.586,-0.421) 9(5.586,0.079) 10(5.586,0.579) 11(5.586,1.079) 12(5.586,1.579) 13(5.586,2.079) 14(5.586,2.579) 15(5.586,3.079) 16(5.586,3.579) 33(-5.514,3.579) 34(-5.514,3.079) 35(-5.514,2.579) 36(-5.514,2.079) 37(-5.514,1.579) 38(-5.514,1.079) 39(-5.514,0.579) 40(-5.514,0.079) 41(-5.514,-0.421) 42(-5.514,-0.921) 43(-5.514,-1.421) 44(-5.514,-1.921) 45(-5.514,-2.421) 46(-5.514,-2.921) 47(-5.514,-3.421) 48(-5.514,-3.921)
  oval 0.3x1.8 smd: 17(3.786,5.379) 18(3.286,5.379) 19(2.786,5.379) 20(2.286,5.379) 21(1.786,5.379) 22(1.286,5.379) 23(0.786,5.379) 24(0.286,5.379) 25(-0.214,5.379) 26(-0.714,5.379) 27(-1.214,5.379) 28(-1.714,5.379) 29(-2.214,5.379) 30(-2.714,5.379) 31(-3.214,5.379) 32(-3.714,5.379) 49(-3.714,-5.721) 50(-3.214,-5.721) 51(-2.714,-5.721) 52(-2.214,-5.721) 53(-1.714,-5.721) 54(-1.214,-5.721) 55(-0.714,-5.721) 56(-0.214,-5.721) 57(0.286,-5.721) 58(0.786,-5.721) 59(1.286,-5.721) 60(1.786,-5.721) 61(2.286,-5.721) 62(2.786,-5.721) 63(3.286,-5.721) 64(3.786,-5.721)
  silkscreen extent -4.21,-4.75 5.71,4.08, body extent -4.96,-5.17 5.04,4.83, height 1.6
MSOP10 [mm]
  rect 1.2x0.25 smd: 1(-2.413,1.829) 2(-2.413,1.329) 3(-2.413,0.829) 4(-2.413,0.329) 5(-2.413,-0.171) 6(1.937,-0.171) 7(1.937,0.329) 8(1.937,0.829) 9(1.937,1.329) 10(1.937,1.829)
  silkscreen extent -1.27,-0.33 0.89,2.08
PSFM-T5 [mm]
  rect 1.5x1.2 hole 1: 1(0,0)
  oval 1.5x1.2 hole 1: 2(0,-1.7) 3(0,-3.4) 4(0,-5.1) 5(0,-6.8)
  silkscreen extent -1.95,-7.98 2.87,1.16
PWR_3T [mm]
  rect 3x3 hole 1.6: 1(0,0)
  round 3 hole 1.6: 2(0,-5) 3(0,-10)
  silkscreen extent -5,-12.67 5.05,3.3
Relay_OMRON5V#1 [mm]
  rect 1.5x1.5 hole 0.7: 1(0,0)
  round 1.5 hole 0.8: 2(0,-2.54) 3(0,-10.16) 4(5.08,-10.16) 5(5.08,-2.54)
  round 1.5 hole 0.7: 6(5.08,0)
  silkscreen extent -1.5,-11.5 6.5,1.5
Relay_OMRON5V#2 [mm]
  rect 2.1x1.9 hole 0.8: 1(0,0)
  oval 2.1x1.9 hole 0.8: 2(0,-2.54) 3(0,-10.16) 4(5.08,-10.16) 5(5.08,-2.54) 6(5.08,0)
  silkscreen extent -1.5,-11.5 6.5,1.5
SMA [mm]
  round 2.2 hole 1.7: 1(2.55,-2.55) 2(0,-5.1) 2(0,0) 2(5.1,-5.1) 2(5.1,0)
SO-8N#1 [mm]
  rect 1.44x0.55 smd: 1(-4.013,3.302)
  oval 1.44x0.55 smd: 2(-4.013,2.022) 3(-4.013,0.742) 4(-4.013,-0.538) 5(1.487,-0.538) 6(1.487,0.742) 7(1.487,2.022) 8(1.487,3.302)
  silkscreen extent -2.46,-1.18 -0.07,3.94
SO-8N#2 [mm]
  rect 1.44x0.55 smd: 1(0,0)
  oval 1.44x0.55 smd: 2(0,-1.28) 3(0,-2.56) 4(0,-3.84) 5(5.5,-3.84) 6(5.5,-2.56) 7(5.5,-1.28) 8(5.5,0)
  silkscreen extent 1.55,-4.48 3.95,0.64
SOT-23-5 [mm]
  rect 0.6x1 smd: 1(-0.995,-1.101)
  oval 0.6x1 smd: 2(-0.045,-1.201) 3(0.905,-1.201) 4(0.905,1.499) 5(-0.995,1.499)
  silkscreen extent -0.4,1.5 0.4,1.5, body extent -1.5,-1.3 1.4,1.5, height 1.2
SOT_23 [mil]
  rect 36x36 smd: 1(0.28,-7.25)
  rect 36x30 smd: 2(0.28,67.75)
  rect 50x36 smd: 3(-79.72,30.75)
  silkscreen extent -85,-27 5,88
SOT_UJ6 [mm] "also adaptable to TSOT_UJ6"
  rect 0.55x1.5 smd: 1(-0.787,-1.27) 2(0.163,-1.27) 3(1.113,-1.27) 4(1.113,1.35) 5(0.163,1.35) 6(-0.787,1.35)
  silkscreen extent -2.34,-2.62 1.88,2.67
TO-220 [mm]
  rect 2x2.5 hole 1.3: 1(-2.565,0)
  oval 2x2.5 hole 1.3: 2(-0.025,0) 3(2.515,0)
  silkscreen extent -5.33,-2 5.27,2.8, body extent -5.11,-1.45 5.05,2.9, height 19.6
TSSOP16 [mm]
  rect 1.2x0.36 smd: 1(-0.021,-0.024)
  oval 1.2x0.36 smd: 2(-0.021,-0.664) 3(-0.021,-1.304) 4(-0.021,-1.944) 5(-0.021,-2.584) 6(-0.021,-3.224) 7(-0.021,-3.864) 8(-0.021,-4.504) 9(5.919,-4.504) 10(5.919,-3.864) 11(5.919,-3.224) 12(5.919,-2.584) 13(5.919,-1.944) 14(5.919,-1.304) 15(5.919,-0.664) 16(5.919,-0.024)
  silkscreen extent 1.41,-4.82 4.48,0.3
USB_A [mil] "USB A type Connector"
  round 60 hole 30: 1(-207.63,-180.91) 4(-207.63,94.09)
  oval 60x52.13 hole 30: 2(-207.63,-80.91) 3(-207.63,-0.91)
  oval 137.79x98.42 hole 78.74: 5(-87.63,239.09) 6(-87.63,-310.91)
  silkscreen extent -282,-341 357,264
USBmicro_B [mm]
  rect 0.4x1.6 smd: 1(1.542,-2.679) 2(0.892,-2.679) 3(0.242,-2.679) 4(-0.408,-2.679) 5(-1.058,-2.679)
  silkscreen extent -4.67,-3.56 5.12,1.93

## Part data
C1 C2 C3 C4 C5 C6 C7 C8 C9 C11 C12 C13 C14 C15 C17 C19 C20 C21 C22 C23 C29 C30 C31 C32 C33 C34 C35 C37 C39 C41 C43 C45 C47 C48 C49 C50 C58 C66 C70 C71 C72 C73 C74 C75 C76 C77 C78 C79 C80 C82 C83 C84 C86 C89 C90 C91 C93 C94 C95 C101 C103 C105 C107 C108 C109 C120 C121 C122 C123 C124 C125: library part Cap, "Capacitor"
C10 C16 C18 C38 C40 C42 C44 C46 C51 C52 C54 C55 C59 C60 C61 C67 C68 C96 C97 C98 C99 C100 C102 C104 C106: library part "Cap Pol1", "Polarized Capacitor (Radial)"
C56 C57 C62 C81 C85: library part Cap, "Capacitor,100V"
D1 D2 D3 D4: "1 Amp General Purpose Rectifier"
DUT_VOL FORCE_H FORCE_L GUARD R_VOL SENSE_H SENSE_L SigIn: "SMB Straight Connector"
J1: library part "D Connector 9", "Receptacle Assembly, 9 Position, Right Angle"
K1 K2 K3 K4 K5 K6 K7 K8 K9 K10: library part "AXiCOM IM05"
K11 K12 K13 K14: library part Relay_OMRON5V, "Relay OMRON"
L1 L2 L3: library part Inductor, "Inductor"
LCD: "Header, 8-Pin"
LED0 LED1: "Header, 2-Pin"
PWR_5V PWR_24V RS485_2: "Header, 3-Pin"
Q1 Q2 Q3 Q4 Q5 Q6 Q7 Q8 Q9 Q10 Q11 Q12 Q13 Q14: library part NUD3105, "Relay Driver 5V Supply"
R1 R2 R10 R12 R14 R16 R17 R18 R19 R21 R27 R29 R30 R31 R32 R33 R34 R35 R36 R37 R38 R39 R40 R41 R42 R43 R44 R45 R46 R47 R49 R50 R51 R52 R53 R54 R55 R56 R57 R58 R59 R60 R100 R101 R102 R103 R104 R105: library part Res1, "Resistor"
U1: library part STM32F103RBT6, "STM32 ARM-based 32-bit MCU with 128 Kbytes Flash, 64-pin LQFP, Industrial Temperature"
U3 U4: library part AD8676
U6 U7: library part AD8422
U9: library part ADR127
U12: "Ultralow Noise, XFET Voltage References"
U13: "Precision CMOS, Single Supply, Rail to Rail, Windband Operational Amplifiers"
U14: library part AD5687R
U17 U18: "AD8137ARZ"
U19 U20: library part AD8601, "Precision CMOS, Single Supply, Rail to Rail, Windband Operational Amplifiers"
USB: library part USB_Normal, "USB interface"

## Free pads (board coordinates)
  round 60 hole 30: 2(9652.86,5819.02)

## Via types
v1: diameter 30/30 (per signal layer), hole 14, Component Side to Solder Side, 595 vias
v2: diameter 50, hole 28, Component Side to Solder Side, 98 vias
v3: diameter 30, hole 14, Component Side to Solder Side, 35 vias
v4: diameter 39.37, hole 29.53, Component Side to Solder Side, 2 vias
v5: diameter 66.93, hole 47.24, Component Side to Solder Side, 2 vias

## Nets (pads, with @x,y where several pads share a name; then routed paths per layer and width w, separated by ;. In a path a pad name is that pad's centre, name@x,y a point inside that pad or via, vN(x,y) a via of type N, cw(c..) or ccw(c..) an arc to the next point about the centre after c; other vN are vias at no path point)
1.25V: C89.2 U9.4 U17.2 U18.2 | length 3573.1
  Component Side w10: v3@10573.51,5790.22 v3(11363.06,5790.22) ; v3@10573.64,5792.83 10573.64,5530.15 U9.4@10677.11,5530.15 ; v3@10574.72,6644.85 v3@11480.76,6644.85 ; v3@11510.03,5788.18 11510.03,5864.4 11586,5940.37 U17.2@11586,5966.4 ; v3@11573.56,6746.29 11573.56,6814.82 11629.52,6870.79 U18.2@11629.52,6888.8
  Solder Side w10: v3@10574.06,5789.42 v3@10574.06,6644.46 ; v3@11366.35,5789.92 v3(11512.48,5789.92) ; v3@11486.82,6646.82 11486.82,6649.25 11574.83,6737.25 v3(11574.83,6745.14)
  other v3: 10573.98,5792.08 10575.39,6645.73 11486.89,6645.67
2.5V: C82.1 C83.1 C91.2 U10.1 U10.2 U11.1 U11.2 U13.1 U13.4 | length 2936.4
  Component Side w10: U13.1@11221.94,5423.71 11221.94,5452.26 11260.54,5490.86 ; 11259.26,5489.36 U13.4@11296.28,5526.38 ; C91.2@11296.36,5666.09 C91.2@11296.75,5663.3 ; C83.1@12076.78,7165.92 C83.1@12077.33,7165.92
  Component Side w20: U13.4@11296.75,5526.07 11296.75,5663.3 v3@11886.38,5663.3 ; v3@11881.35,7165.92 12076.78,7165.92 U11.1@12076.78,7085.54 U11.2@12076.78,7068.66 ; v3@11886.32,6204.55 C82.1@12070.94,6204.55 ; U10.2@12072.14,6110.3 C82.1@12072.14,6204.12
  Solder Side w20: v3@11886.2,5664.3 v3@11886.2,7163.87
  other v3: 11886.75,5665.5 11888.28,6203.78 11883.89,7163.74
5V: C9.2 C10.1 C11.2 C13.2 C60.1 C61.1 C62.2 C86.2 C93.1 C94.2 C95.2 C107.2 C120.2 L2.1 PWR_5V.3 U9.3 U12.2 U13.5 U14.5 U17.3 U18.3 U19.5 U20.5 | length 17885.9
  Component Side w10: C107.2@11431.87,5968.36 C107.2@11431.87,5970.12 11467.31,5970.12 11538.33,6041.13 11617.41,6041.13 11637.35,6021.19 11637.35,5935.23 11607.09,5904.98 C120.2@11607.09,5872.66 ; C11.2@11450.64,6893 11491.19,6893 11561.53,6963.34 11652.93,6963.34 11678.95,6937.32 11678.95,6875.27 11647.59,6843.91 C13.2@11647.59,6802.55 ; C94.2@11836.79,5322.72 C94.2@11838.75,5320.76 ; U14.5@11987.2,7786.7 12055.02,7786.7 12097.01,7744.71 C9.2@12097.01,7629.59 ; C95.2@11836.79,5455.17 11836.79,5456.01 11837.63,5455.17 C95.2@11836.79,5455.17
  Component Side w20: C86.2@10779.72,5622.61 v2@10928.06,5622.61 ; U9.3@10780.26,5530.15 C86.2@10780.26,5620.38 ; v2@10920.97,5325.13 C94.2@11837.25,5325.13 ; v2(10922.16,5519.59) C93.1@11128.48,5519.59 ; v2@10923.08,7498.09 C10.1@12080.46,7498.09 ; v2@10923.24,6789.23 11342.29,6789.23 11381.47,6828.4 U20.5@11381.47,6893.43 C11.2@11450.37,6893.43 ; v2@10923.5,5913.89 11335.08,5913.89 11356.78,5935.59 U19.5@11356.78,5968.36 C107.2@11431.87,5968.36 ; C93.1@11121.77,5524.52 U13.5@11226.15,5524.52 ; U12.2@11712.87,5455.17 11836.79,5455.17 C94.2@11836.79,5322.72 ; C10.1@12095.39,7487.51 C9.2@12095.39,7627.9
  Component Side w30: v2@10924.86,10664.91 13303.8,10661.74 13307.28,10661.73 C61.1@13307.28,11751.68
  Component Side w40: PWR_5V.3@12786.52,11751.73 C61.1@13277.32,11751.73
  Component Side w50: C61.1@13282.28,11746.73 C61.1@13286.74,11742.27
  Component Side w80: v2@13370.33,9583.76 13681.88,9272.2 L2.1@13681.88,9240.31
  Solder Side w30: v2@10922.16,5325.69 v2(10922.16,5519.59) ; v2@10923.43,5524.68 v2(10923.43,10663.3)
  Solder Side w40: v2(13681.88,9265.31) v2@13686.88,9260.31
  Solder Side w100: PWR_5V.3@12785.58,11752.26 12785.58,10168.59 v2@13682.88,9266.3
  other v2: 10921.2,5327.36 10924.76,5621.87 10924.08,5912.62 10922.16,6782.16 10922.29,7497.7 13628.41,9320.31 13566.88,9383.59 13506.88,9445.31 13440.52,9513.57 13373.78,9580.31
+15V: C15.2 C16.1 C19.2 C37.2 C38.1 C39.2 C40.1 C43.2 C44.1 C97.1 C100.1 C103.2 C104.1 D1.2 D3.1 K1.1 K2.1 K3.1 K4.1 K5.1 K6.1 K7.1 K8.1 K9.1 K10.1 K11.2 K12.2 K13.2 K14.2 pad.2 U2.5 U3.8 U4.8 U6.8 U7.8 U15.3 | length 21230.8
  Component Side w10: C40.1@8226.14,9264.33 C40.1@8227.53,9264.33 ; C37.2@9711.82,9118.09 C37.2@9715.55,9118.09 ; C97.1@9966.42,11171.72 C97.1@9972.01,11166.13 ; U15.3@10215.11,11166.13 U15.3@10215.11,11169.72 ; C104.1@11974.56,9481.56 C104.1@11978.92,9485.91
  Component Side w20: U6.8@8227.53,9009.71 8227.53,9264.33 v2@8709.72,9264.33 ; K1.1@9715.55,8989.96 C37.2@9715.55,9118.09 ; C38.1@9715.55,9255.12 C37.2@9715.55,9118.09 ; v2@10215.7,9118.09 C37.2@9715.55,9118.09 ; C100.1@10324.81,9336.99 U4.8@10573.43,9336.99 ; C16.1@11297.98,9243.47 U3.8@11535.73,9243.47
  Component Side w30: v2(8022.49,7248.24) v2@8711.95,7248.24 ; U7.8@8333.23,7849.28 C44.1@8333.23,8088.34 ; C43.2@8333.53,7943.98 v2@8715.92,7943.98 ; v2@8709.53,9957.98 8769.82,9957.98 ; 8763.19,9959.07 v2(10213.53,9959.07) ; v2@9655.35,6519.15 K8.1@9715.55,6519.15 ; v2@9658.34,7931.04 K4.1@9715.55,7931.04 ; v2@9661.38,8284.01 K3.1@9715.55,8284.01 ; pad.2@9662.01,5813.21 K10.1@9715.55,5813.21 ; v2@9662.19,8636.98 K2.1@9715.55,8636.98 ; v2@9662.55,8989.96 K1.1@9715.55,8989.96 ; v2@9662.63,7578.07 K5.1@9715.55,7578.07 ; v2@9663,7225.1 K6.1@9715.55,7225.1 ; v2@9663.99,6872.13 K7.1@9715.55,6872.13 ; v2@9666.86,6166.18 K9.1@9715.55,6166.18 ; v2@10211.2,9332.99 C100.1@10328.77,9332.99 ; v2(10211.42,8913.88) v2@11034.08,8913.88 ; v2(10214.65,10527.42) v2@12152.04,10527.42 ; v2@10215.11,10531.16 U15.3@10215.11,11166.13 ; v2@11026.03,9244.12 C16.1@11293.58,9244.12 ; C104.1@11978.92,9485.91 U2.5@11978.92,9782.7 v2@12155.37,9782.7
  Component Side w40: C97.1@9966.42,11171.72 D1.2@9966.42,11336.6 ; C97.1@9972.01,11166.13 10215.11,11166.13 10217.25,11166.13 10217.25,11280 10261.66,11324.4 D3.1@10298.04,11324.4
  Solder Side w10: K14.2@8016.68,6762.69 K14.2@8016.68,6769.26 ; v2@10213.02,10529.82 v2@10213.02,10533.35 ; v2@12151.89,9785.42 v2@12152.94,9784.37
  Solder Side w30: K13.2@8014.82,6387.86 7940.13,6387.86 7861.75,6466.24 7861.75,6721.22 7909.79,6769.26 8016.68,6769.26 v2@8016.68,7248.2 ; v2@8712.38,7941.8 v2@8712.38,9958.17 ; v2@8714.42,7247.52 v2(8714.42,7943.9) ; pad.2@9652.86,5819.02 v2@9652.86,8991.97 ; v2@10213.06,8914.84 v2(10213.06,9694.92) v2@10213.06,10533.38 ; K12.2@10633.32,8748.01 v2(10633.32,8911) ; v2@11020.67,9242.88 v2(11020.67,10526.17) ; K11.2@11038.89,8734.09 v2(11038.89,8914.84) ; v2@12151.89,9785.42 v2(12151.89,10532.44)
  other v2: 9658.64,6169.66 9650.76,6520.28 9655.15,6879.09 9652.82,7224.5 8714.33,7249.67 9658.64,7575.72 9652.82,7932.76 9652.82,8285.14 9655.15,8636.37 9651.66,8987.59 10214.77,9118.43 11019.55,9242.88 8710.22,9266.9 10211.2,9330.3 12154.18,9783.66 8710.92,9956.97
+24V: C66.1 C67.1 C68.1 C96.1 D3.2 PWR_24V.3 U15.1 | length 1085.7
  Component Side w40: PWR_24V.3@9927.23,11769.48 9928.53,11768.18 C68.1@10412.99,11768.18 ; U15.1@10412.06,11160.59 C68.1@10412.06,11760.01
-5V: C12.2 C14.2 C54.2 C55.2 C56.2 C109.2 C121.2 PWR_5V.1 U17.6 U18.6 U19.2 U20.2 | length 8644.1
  Component Side w10: C121.2@11596.39,6275.96 11636.39,6235.96 U17.6@11636.39,6182.93 ; C14.2@11645.61,7198.16 11679.92,7163.85 U18.6@11679.92,7105.34 ; v2@11878.93,10721.28 v2(11880.25,10721.28)
  Component Side w20: v2@11176.13,6404.91 v3(11598.84,6404.91) ; v2@11176.75,6167.65 C109.2@11318.64,6167.65 ; v2@11179.51,7347.7 v3(11648.34,7347.7) ; v2@11184.71,7086.22 11344.07,7086.22 U20.2@11344.07,6999.73 ; U19.2@11319.38,6074.66 C109.2@11319.38,6173.52 ; C121.2@11599.08,6273.63 v3@11599.08,6340.76 ; C14.2@11645.61,7198.16 v3@11645.61,7259.7
  Component Side w30: v2@11183.63,10721.28 v2@11878.93,10721.28
  Component Side w40: v2@11878.93,10721.28 C54.2@11878.93,11746.73 ; C54.2@11883.88,11751.73 C56.2@12177.82,11751.73 PWR_5V.1@12392.82,11751.73
  Solder Side w20: v3(11598.36,6343.63) v3@11598.36,6398.05 ; v3(11646.94,7259.57) v3@11646.94,7341.17
  Solder Side w30: v2@11179.89,6169.24 11179.89,6172.91 11180.16,6397.99 11180.95,7082.15 11180.95,7084.29 11181.05,7159.27 11185.52,10719.07 v2@11185.53,10722.86
  other v2: 11180.56,6172.91 11181.87,6397.99 11183.86,7084.29 11183.11,7349.97 11187.42,10719.07
-15V: C17.2 C18.2 C41.2 C42.2 C45.2 C46.2 C99.2 C101.2 C102.2 C105.2 C106.2 D2.1 D4.2 R27.1 U2.3 U3.4 U4.4 U6.5 U7.5 U16.3 | length 12783.8
  Component Side w10: D2.1@8683.67,11319.78 D2.1@8684,11319.45 ; C17.2@11788.87,9026.94 C17.2@11789.1,9026.71 ; C18.2@11925.65,9027.38 C18.2@11925.87,9027.6
  Component Side w20: C106.2@11361.43,9841.25 R27.1@11603.3,9841.25 ; R27.1@11603.3,9842.67 11831.29,9842.67 11847.63,9826.34 11847.63,9785.27 U2.3@11845.06,9782.7 ; U3.4@11686.91,9026.94 C17.2@11788.87,9026.94 ; C17.2@11782.6,9027.38 C18.2@11925.65,9027.38
  Component Side w30: v2@8072.04,8619.82 C42.2@8221.24,8619.82 ; v2@8073.07,7466.95 C46.2@8325.67,7466.95 ; v2@8074.24,10150.13 v2(8927.26,10150.13) 11204.27,10150.13 ; C42.2@8227.53,8617.87 U6.5@8227.53,8858.53 ; C46.2@8333.23,7454.72 U7.5@8333.23,7698.1 ; v2@8922.53,10552.12 U16.3@8922.53,11169.72 ; U4.4@10789.97,9490.2 C102.2@10789.97,9719.91 ; C102.2@10792.22,9716.85 v2@11097.59,9716.85 ; v2@11103.97,9841.25 C106.2@11361.43,9841.25 ; 11198.54,10150.54 v2@12250.49,10150.54 ; C18.2@11921.45,9023.21 v2@12251.43,9023.21
  Component Side w40: C99.2@8682.55,11169.72 U16.3@8922.53,11169.72 D4.2@8922.53,11329.05 ; C99.2@8684,11171.27 D2.1@8684,11319.45
  Solder Side w30: v2@8075.87,7464.65 v2(8075.87,10148.86) ; v2@8924.24,10145.99 v2(8924.24,10542.4) ; v2@12247.98,10146.83 v2@12248.06,9019.5
  Solder Side w40: v2(11101.45,9715.82) v2@11101.45,10152.45
  other v2: 8078.57,7469.85 8077.44,8622.09 12245.71,9028.63 11103.97,9839.49 12251.27,10147.56 11100.18,10153.72
-24V: C50.1 C51.2 C52.2 C98.2 D4.1 PWR_24V.1 U16.2 | length 1056.8
  Component Side w40: U16.2@9027.12,11162.53 9027.12,11761.91 C52.2@9029.64,11764.43 ; C52.2@9034.69,11764.48 C50.1@9323.53,11764.48 PWR_24V.1@9488.53,11764.48
ADC1_CNV: U1.38 U10.6 | length 1674.3
  Component Side w10: U10.6@12245.42,6046.61 13483.44,6046.61 13639.4,6202.57 U1.38@13639.4,6418.24
ADC1_SCK: U1.36 U10.8 | length 1593.8
  Component Side w10: U10.8@12238.36,6086.26 13429.6,6086.26 13600.03,6256.69 U1.36@13600.03,6418.24
ADC1_SDI: U1.35 U10.9 | length 1553.7
  Component Side w10: U10.9@12241.45,6106.09 12241.68,6105.86 13413.58,6105.86 13580.34,6272.62 U1.35@13580.34,6418.24
ADC1_SDO: U1.37 U10.7 | length 1629.8
  Component Side w10: U10.7@12247.96,6066.35 13459.55,6066.35 13619.71,6226.51 U1.37@13619.71,6418.24
ADC2_CNV: U1.23 U11.6 | length 1363.8
  Component Side w10: U11.6@12247.28,7006.6 12348.28,7006.6 12688.61,6666.27 U1.23@13470.11,6666.27
ADC2_SCK: U1.21 U11.8 | length 1363.6
  Component Side w10: U11.8@12247.5,7046.09 12387.76,7046.09 12728.2,6705.64 U1.21@13470.11,6705.64
ADC2_SDI: U1.20 U11.9 | length 1363.7
  Component Side w10: U11.9@12247.34,7065.6 12401.7,7065.6 12741.98,6725.33 U1.20@13470.11,6725.33
ADC2_SDO: U1.22 U11.7 | length 1366.6
  Component Side w10: U11.7@12244.49,7026.41 12366.37,7026.41 12706.83,6685.96 U1.22@13470.11,6685.96
AGND: C7.2 C8.2 C9.1 C10.2 C11.1 C12.1 C13.1 C14.1 C15.1 C16.2 C17.1 C18.1 C19.1 C20.1 C21.2 C31.1 C32.2 C33.1 C35.2 C37.1 C38.2 C39.1 C40.2 C41.1 C42.1 C43.1 C44.2 C45.1 C46.1 C47.2 C48.2 C49.2 C50.2 C51.1 C52.1 C54.1 C55.1 C56.1 C60.2 C61.2 C62.1 C66.2 C67.2 C68.2 C80.2 C82.2 C83.2 C84.2 C86.1 C89.1 C90.1 C91.1 C93.2 C94.1 C95.1 C96.2 C97.2 C98.1 C99.1 C100.2 C101.1 C102.1 C103.1 C104.2 C105.1 C106.1 C107.1 C109.1 C120.1 C121.1 D1.1 D2.2 DUT_VOL.2 FORCE_L.1 FORCE_L.2 GUARD.2 L3.1 PWR_5V.2 PWR_24V.2 Q1.2 Q2.2 Q3.2 Q4.2 Q5.2 Q6.2 Q7.2 Q8.2 Q9.2 Q10.2 Q11.2 Q12.2 Q13.2 Q14.2 R17.2 R50.1 R52.1 R55.2 R59.2 R_VOL.2 SENSE_L.2 SigIn.2 U6.6 U7.6 U9.2 U10.5 U11.5 U12.4 U13.2 U14.4 U14.9 U14.16 U15.2 U16.1 | length 823.8
  Component Side w10: 9659.47,11707.46 PWR_24V.2@9722.05,11770.04 9789.51,11837.49 ; U14.4@11987.2,7811.9 v1@12087.01,7811.9 ; 12527.88,11811.66 12652.32,11687.22
  Solder Side w10: 9659.47,11832.62 PWR_24V.2@9722.05,11770.04 9739.58,11770.04 9802.37,11707.25 ; 12522.82,11696.73 12642.47,11816.39
  other v1: 9119.58,4937.76 9199.58,4937.76 9279.58,4937.76 10719.16,4942.81 10799.16,4942.81 10879.16,4942.81 8083.71,5222.19 7944.46,5225.97 12253.2,5249.04 12113.94,5252.82 10588.92,5275.46 10668.92,5275.46 10748.92,5275.46 8083.71,5302.19 7944.46,5305.97 12253.2,5329.04 12113.94,5332.82 7204.06,5373.16 7284.06,5373.16 7364.06,5373.16 8083.71,5382.19 7944.46,5385.97 12253.2,5409.04 10390.39,5410.25 12113.94,5412.82 10251.14,5414.03 7204.06,5453.16 7284.06,5453.16 7364.06,5453.16 10390.39,5490.25 10251.14,5494.03 11837.92,5565.35 11917.92,5565.35 10390.39,5570.25 10251.14,5574.03 12122.11,5630.79 12122.11,5710.79 11605.14,5743.06 9860.3,5767.35 9940.3,5767.35 12122.11,5790.79 11186.21,5863.24 12039.21,5946.38 11795.23,6013.71 10750.82,6081.22 11795.23,6093.71 11446.19,6108.51 9844.47,6109.95 9924.47,6109.95 11037.1,6136.15 10750.82,6161.22 8234.43,6196.24 8314.43,6196.24 8394.43,6196.24 11037.1,6216.15 10750.82,6241.22 12160.46,6241.32 7334.51,6264.88 7195.26,6268.67 11962.31,6281.78 11037.1,6296.15 11315.91,6321.35 11533.49,6340.51 7334.51,6344.88 7195.26,6348.67 11961.31,6354.12 7334.51,6424.88 7195.26,6428.67 9850.85,6441.38 9930.85,6441.38 8250.75,6604.33 8330.75,6604.33 8410.75,6604.33 11075.34,6691.31 10998.55,6692.69 11585.69,6693.52 11449.89,6711.51 12044.06,6775.25 12124.06,6775.25 9851.08,6792.01 9931.08,6792.01 11239.12,6829.82 11019,6859.19 7909.39,6862.93 7909.39,6942.93 12041.89,6942.54 8256.22,6961.34 8116.96,6965.12 11520.01,6995.38 11014.33,7005.3 7909.39,7022.93 8256.22,7041.34 8116.96,7045.12 8256.22,7121.34 8116.96,7125.12 11062.69,7127.02 9838.42,7154.71 9918.42,7154.71 11062.69,7207.02 11975,7254.79 11586.63,7265.68 10273.4,7272.51 10134.14,7276.3 8364.32,7330.67 8444.32,7330.67 8524.32,7330.67 10273.4,7352.51 10134.14,7356.3 12109.82,7388.63 12189.82,7388.63 12269.82,7388.63 11373.68,7424.31 11453.68,7424.31 11533.68,7424.31 11752.71,7428.18 11832.71,7428.18 11912.71,7428.18 10273.4,7432.51 10134.14,7436.3 7215.39,7453.44 7354.65,7453.89 9850.7,7513.37 9930.7,7513.37 7215.39,7533.44 7354.65,7533.89 11672.78,7551.96 11752.78,7551.96 11832.78,7551.96 7215.39,7613.44 7354.65,7613.89 11833.76,7622.04 10666.52,7669.87 10527.26,7673.65 8409.75,7701.67 8489.75,7701.67 11044.99,7714.58 10666.52,7749.87 10527.26,7753.65 11044.99,7794.58 12083.42,7811.72 10666.52,7829.87 10527.26,7833.65 11743.04,7847.69 8482.25,7852.73 8562.25,7852.73 8642.25,7852.73 9851.42,7861.04 9931.42,7861.04 11044.99,7874.58 8145.09,7943.31 11921.53,8013.66 12001.53,8013.66 12081.53,8013.66 7887.12,8102.99 7747.87,8106.77 7887.12,8182.99 7747.87,8186.77 9859.68,8215.68 9939.68,8215.68 7887.12,8262.99 8432.68,8266.19 7747.87,8266.77 8293.42,8269.97 11005.06,8319.16 11085.06,8319.16 10677.66,8324.81 10757.66,8324.81 8432.68,8346.19 8293.42,8349.97 8432.68,8426.19 8293.42,8429.97 11436.11,8540.01 11296.85,8543.79 9840.05,8560.82 9927.38,8563.13 8635.19,8585.5 12101.6,8612.33 7376,8612.94 7456,8612.94 11962.35,8616.11 11436.11,8620.01 11296.85,8623.79 8635.19,8665.5 12101.6,8692.33 7376,8692.94 7456,8692.94 11962.35,8696.11 11436.11,8700.01 11296.85,8703.79 8635.19,8745.5 12101.6,8772.33 7376,8772.94 7456,8772.94 11962.35,8776.11 9851.42,8928.82 9924.07,8928.82 11406.63,9059.78 7541.83,9090.84 7621.83,9090.84 7701.83,9090.84 9373.27,9124.47 10463.73,9137.38 10553.49,9139.87 12084.75,9161.44 8024.3,9162.09 8884.53,9166.32 8817.55,9170.1 8331.11,9182.07 8411.11,9182.07 11816.66,9201.95 9373.27,9204.47 12084.75,9241.44 8884.53,9246.32 8817.55,9250.1 12084.75,9321.44 8884.53,9326.32 8817.55,9330.1 11359.45,9519.74 11457.12,9521.14 11537.12,9521.14 9478.28,9720.68 9558.28,9720.68 9638.28,9720.68 8404.08,9738.79 8264.82,9742.57 10489.87,9770.27 10350.61,9774.06 12686.6,9807.38 12547.35,9811.16 8404.08,9818.79 8264.82,9822.57 10489.87,9850.27 10350.61,9854.06 9482.06,9859.93 9562.06,9859.93 9642.06,9859.93 7364.03,9883.99 7212.47,9885.9 12686.6,9887.38 12547.35,9891.16 8404.08,9898.79 8264.82,9902.57 10489.87,9930.27 10350.61,9934.06 11779.57,9939.59 7364.03,9963.99 7212.47,9965.9 12686.6,9967.38 12547.35,9971.16 14276.88,9990.31 14356.88,9990.31 14436.88,9990.31 7364.03,10043.99 7212.47,10045.9 14276.88,10070.31 14356.88,10070.31 14436.88,10070.31 9406.3,10240 9486.3,10240 9566.3,10240 11395.51,10271.23 11475.51,10271.23 11555.51,10271.23 7844.31,10443.25 7705.06,10447.04 15458.97,10461.71 15538.97,10461.71 7844.31,10523.25 7705.06,10527.04 15458.97,10541.71 15538.97,10541.71 9670.95,10590.91 9531.69,10594.69 7844.31,10603.25 7705.06,10607.04 15458.97,10621.71 15538.97,10621.71 13581.88,10635.31 13661.88,10635.31 9670.95,10670.91 9531.69,10674.69 14261.46,10702.8 14341.46,10702.8 14421.46,10702.8 13581.88,10715.31 13661.88,10715.31 9670.95,10750.91 9531.69,10754.69 14261.46,10782.8 14341.46,10782.8 14421.46,10782.8 14261.46,10862.8 14341.46,10862.8 14421.46,10862.8 13095.51,11050.26 12956.26,11054.04 12255.55,11100.39 12335.55,11100.39 12415.55,11100.39 12495.55,11100.39 13095.51,11130.26 7415.11,11133.89 7495.11,11133.89 7575.11,11133.89 12956.26,11134.04 12255.55,11180.39 12335.55,11180.39 12415.55,11180.39 12495.55,11180.39 11072.72,11180.82 11152.72,11180.82 11232.72,11180.82 13095.51,11210.26 7415.11,11213.89 7495.11,11213.89 7575.11,11213.89 12956.26,11214.04 9401.31,11242.46 9481.31,11242.46 9561.31,11242.46 15005.51,11254.49 15085.51,11254.49 15165.51,11254.49 15245.51,11254.49 11072.72,11260.82 11152.72,11260.82 11232.72,11260.82 7415.11,11293.89 7495.11,11293.89 7575.11,11293.89 9401.31,11322.46 9481.31,11322.46 9561.31,11322.46 15005.51,11334.49 15085.51,11334.49 15165.51,11334.49 15245.51,11334.49 11072.72,11340.82 11152.72,11340.82 11232.72,11340.82 9401.31,11402.46 9481.31,11402.46 9561.31,11402.46 15005.51,11414.49 15085.51,11414.49 15165.51,11414.49 15245.51,11414.49 12487.82,11506.73 12567.82,11506.73 12647.82,11506.73 12487.82,11586.73 12567.82,11586.73 12647.82,11586.73 9653.53,11629.48 9733.53,11629.48 9813.53,11629.48 11210.94,11680.83 11290.94,11680.83 11370.94,11680.83 8319.34,11685.05 8399.34,11685.05 8479.34,11685.05 11210.94,11760.83 11290.94,11760.83 11370.94,11760.83 8319.34,11765.05 8399.34,11765.05 8479.34,11765.05 14213.96,11902.57 14293.96,11902.57 14373.96,11902.57 14453.96,11902.57 7752.74,11903.76 7832.74,11903.76 7912.74,11903.76 7992.74,11903.76 14213.96,11982.57 14293.96,11982.57 14373.96,11982.57 14453.96,11982.57 7752.74,11983.76 7832.74,11983.76 7912.74,11983.76 7992.74,11983.76 14213.96,12062.57 14293.96,12062.57 14373.96,12062.57 14453.96,12062.57 7752.74,12063.76 7832.74,12063.76 7912.74,12063.76 7992.74,12063.76
  other v3: 11268.78,7148.24
CTRL1: Q1.1 U1.8 | length 5167.9
  Component Side w10: Q1.1@9925.34,8714.79 10122.69,8714.79 10589.87,8247.62 10634.41,8247.62 ; 10614.16,8247.14 13338.41,8247.14 13698.45,7887.1 U1.8@13698.45,6855.25
CTRL2: Q2.1 U1.9 | length 4949.3
  Component Side w10: Q2.1@9925.34,8361.71 10209.97,8361.71 10372.48,8199.2 ; 10370.98,8200.34 13306.59,8200.34 13678.77,7828.17 U1.9@13678.77,6855.25
CTRL3: Q3.1 U1.10 | length 4885.1
  Component Side w10: Q3.1@9925.34,8008.63 10207.77,8008.63 10364.34,8165.19 13277.62,8165.19 13659.08,7783.73 U1.10@13659.08,6855.25
CTRL4: Q4.1 U1.11 | length 4941.1
  Component Side w10: Q4.1@9925.34,7655.54 10097.77,7655.54 10550.78,8108.55 11722.49,8108.55 ; 11714.19,8108.83 13259.61,8108.83 13639.4,7729.04 U1.11@13639.4,6855.25
CTRL5: Q5.1 U1.24 | length 3914.2
  Component Side w10: Q5.1@9913.04,7312.61 Q5.1@9925.92,7299.73 ; Q5.1@9922.62,7301.75 9922.62,7224.51 10539.01,6608.12 12136.1,6608.12 12174.57,6646.59 U1.24@13470.11,6646.59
